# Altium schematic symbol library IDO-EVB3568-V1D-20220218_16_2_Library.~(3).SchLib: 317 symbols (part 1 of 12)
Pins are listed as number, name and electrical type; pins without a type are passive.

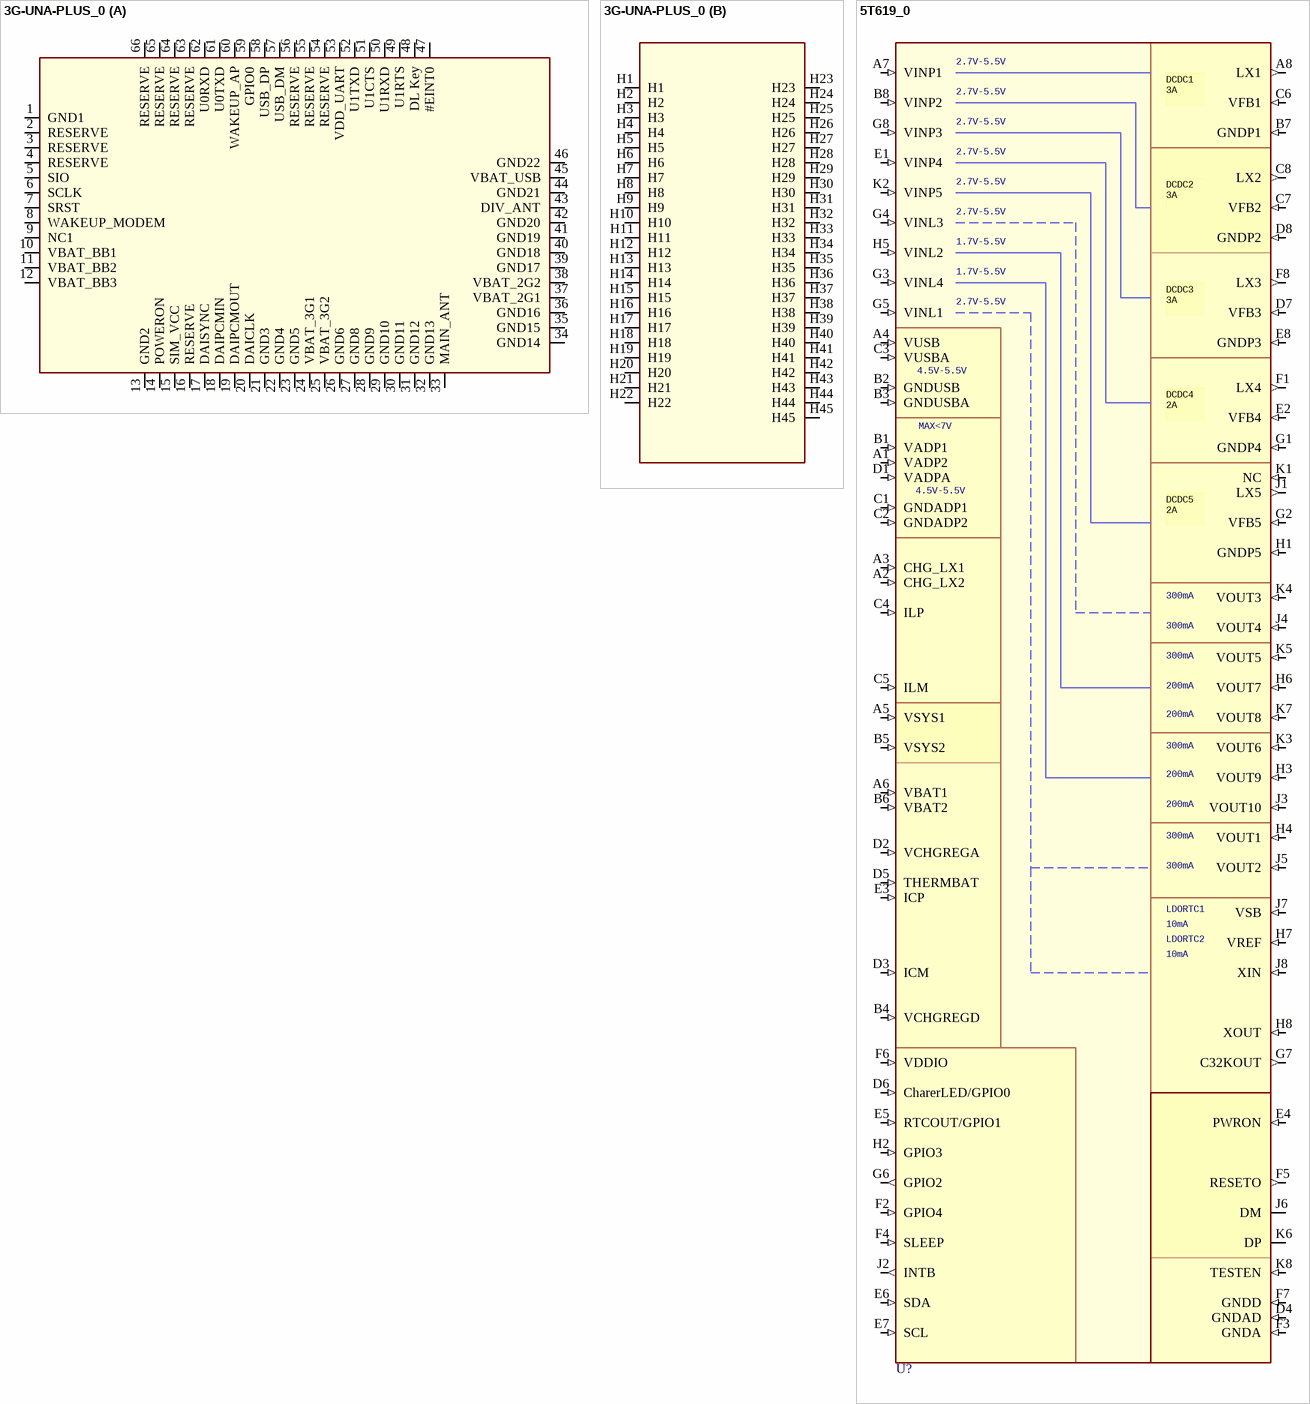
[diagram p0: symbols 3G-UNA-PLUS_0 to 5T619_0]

## 3G-UNA-PLUS_0
designator U?
Altium-Right: 340; Altium-Bottom: 210; Altium-Right1: 110; Altium-Bottom1: 280
part A pins: 1 GND1, 2 RESERVE, 3 RESERVE, 4 RESERVE, 5 SIO, 6 SCLK, 7 SRST, 8 WAKEUP_MODEM, 9 NC1, 10 VBAT_BB1, 11 VBAT_BB2, 12 VBAT_BB3, 13 GND2, 14 POWERON, 15 SIM_VCC, 16 RESERVE, 17 DAISYNC, 18 DAIPCMIN, 19 DAIPCMOUT, 20 DAICLK, 21 GND3, 22 GND4, 23 GND5, 24 VBAT_3G1, 25 VBAT_3G2, 26 GND6, 27 GND8, 28 GND9, 29 GND10, 30 GND11, 31 GND12, 32 GND13, 33 MAIN_ANT, 34 GND14, 35 GND15, 36 GND16, 37 VBAT_2G1, 38 VBAT_2G2, 39 GND17, 40 GND18, 41 GND19, 42 GND20, 43 DIV_ANT, 44 GND21, 45 VBAT_USB, 46 GND22, 47 #EINT0, 48 DL Key, 49 U1RTS, 50 U1RXD, 51 U1CTS, 52 U1TXD, 53 VDD_UART, 54 RESERVE, 55 RESERVE, 56 RESERVE, 57 USB_DM, 58 USB_DP, 59 GPIO0, 60 WAKEUP_AP, 61 U0TXD, 62 U0RXD, 63 RESERVE, 64 RESERVE, 65 RESERVE, 66 RESERVE
part B pins: H1, H2, H3, H4, H5, H6, H7, H8, H9, H10, H11, H12, H13, H14, H15, H16, H17, H18, H19, H20, H21, H22, H23, H24, H25, H26, H27, H28, H29, H30, H31, H32, H33, H34, H35, H36, H37, H38, H39, H40, H41, H42, H43, H44, H45

## 5T619_0
designator U?  (value not drawn)
Altium-Right: 250; Altium-Bottom: 880
pins: A1 VADP2 (in), A2 CHG_LX2 (in), A3 CHG_LX1 (in), A4 VUSB (in), A5 VSYS1 (in), A6 VBAT1 (in), A7 VINP1 (in), A8 LX1 (out), B1 VADP1 (in), B2 GNDUSB (in), B3 GNDUSBA (in), B4 VCHGREGD (in), B5 VSYS2 (in), B6 VBAT2 (in), B7 GNDP1 (in), B8 VINP2 (in), C1 GNDADP1 (in), C2 GNDADP2 (in), C3 VUSBA (in), C4 ILP (in), C5 ILM (in), C6 VFB1 (in), C7 VFB2 (in), C8 LX2 (out), D1 VADPA (in), D2 VCHGREGA (in), D3 ICM (in), D4 GNDAD (in), D5 THERMBAT (in), D6 CharerLED/GPIO0 (in), D7 VFB3 (in), D8 GNDP2 (in), E1 VINP4 (in), E2 VFB4 (in), E3 ICP (in), E4 PWRON (in), E5 RTCOUT/GPIO1 (in), E6 SDA (in), E7 SCL (in), E8 GNDP3 (in), F1 LX4 (out), F2 GPIO4 (in), F3 GNDA (in), F4 SLEEP (in), F5 RESETO (out), F6 VDDIO (in), F7 GNDD (in), F8 LX3 (out), G1 GNDP4 (in), G2 VFB5 (in), G3 VINL4 (in), G4 VINL3 (in), G5 VINL1 (in), G6 GPIO2 (out), G7 C32KOUT (out), G8 VINP3 (in), H1 GNDP5 (in), H2 GPIO3 (in), H3 VOUT9 (in), H4 VOUT1 (in), H5 VINL2 (in), H6 VOUT7 (in), H7 VREF (in), H8 XOUT (in), J1 LX5 (out), J2 INTB (out), J3 VOUT10 (in), J4 VOUT4 (in), J5 VOUT2 (in), J6 DM, J7 VSB (in), J8 XIN (in), K1 NC (in), K2 VINP5 (in), K3 VOUT6 (in), K4 VOUT3 (in), K5 VOUT5 (in), K6 DP, K7 VOUT8 (in), K8 TESTEN (in)

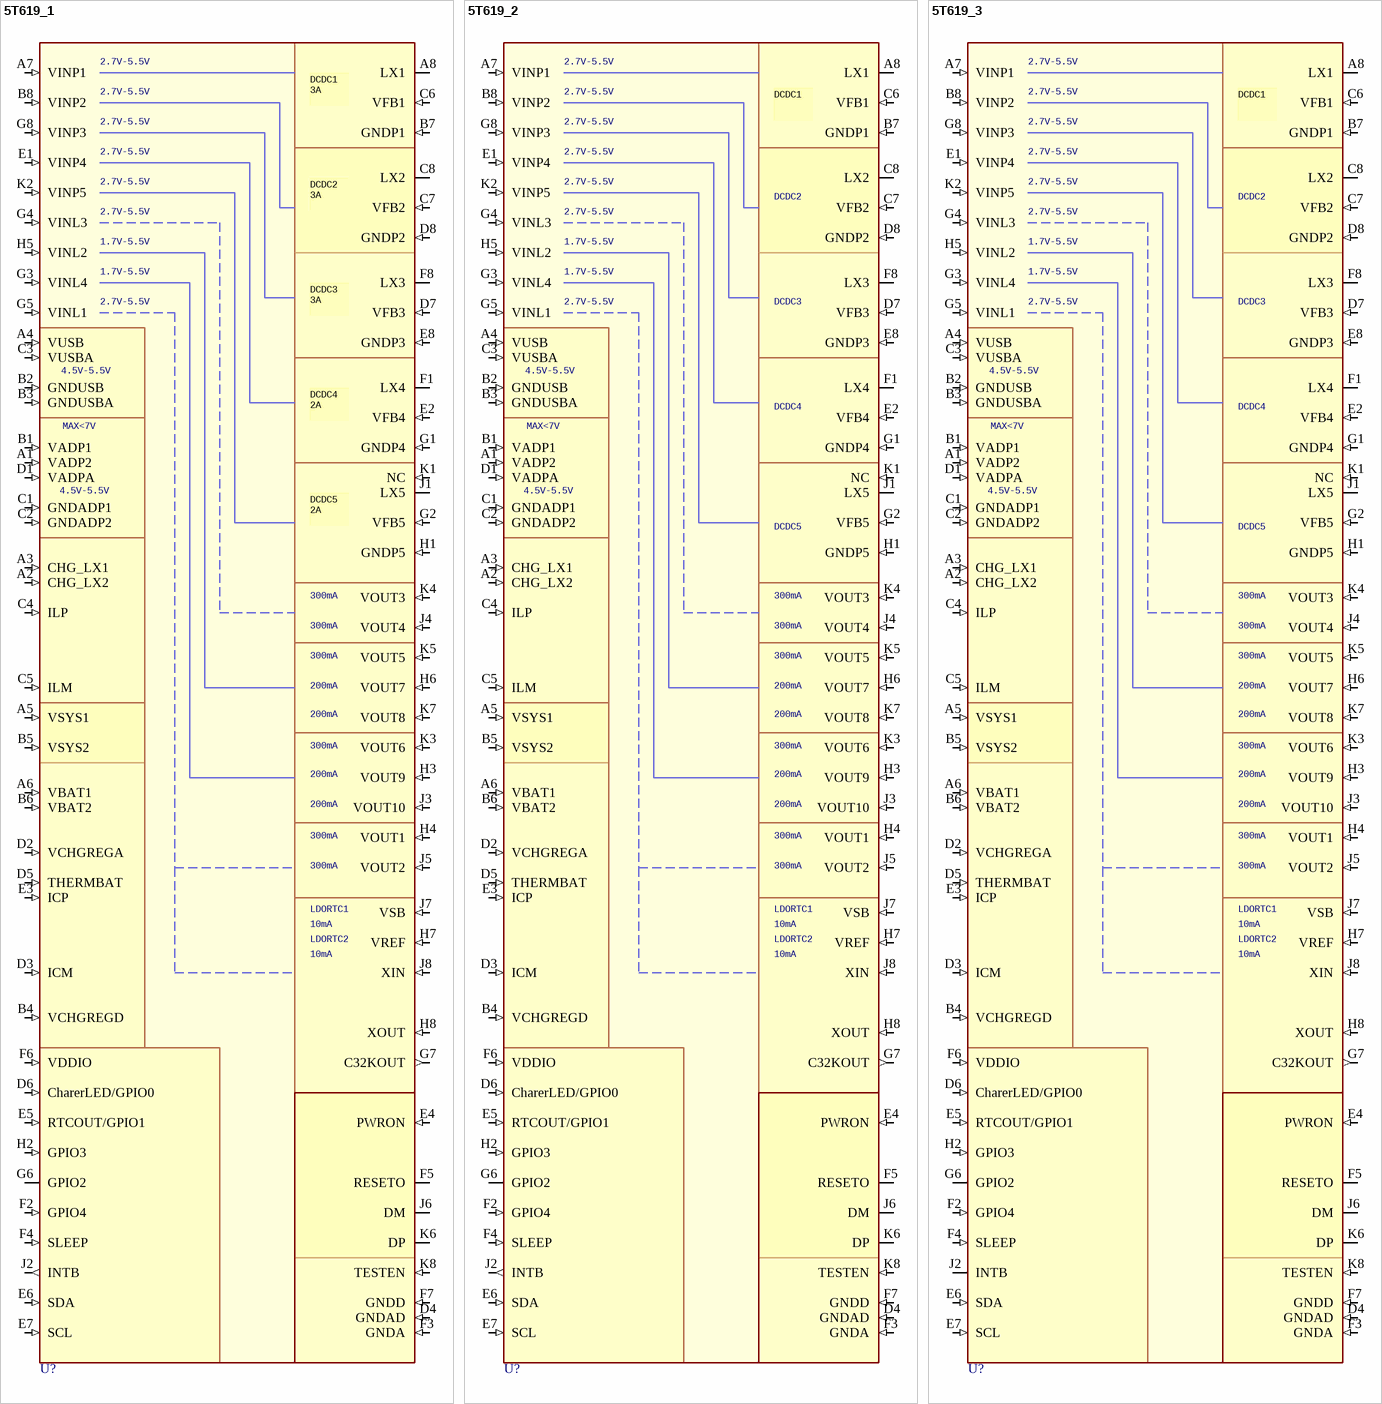
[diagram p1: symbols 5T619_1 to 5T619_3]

## 5T619_1
designator U?  (value not drawn)
Altium-Right: 250; Altium-Bottom: 880
pins: A1 VADP2 (in), A2 CHG_LX2 (in), A3 CHG_LX1 (in), A4 VUSB (in), A5 VSYS1 (in), A6 VBAT1 (in), A7 VINP1 (in), A8 LX1, B1 VADP1 (in), B2 GNDUSB (in), B3 GNDUSBA (in), B4 VCHGREGD (in), B5 VSYS2 (in), B6 VBAT2 (in), B7 GNDP1 (in), B8 VINP2 (in), C1 GNDADP1 (in), C2 GNDADP2 (in), C3 VUSBA (in), C4 ILP (in), C5 ILM (in), C6 VFB1 (in), C7 VFB2 (in), C8 LX2, D1 VADPA (in), D2 VCHGREGA (in), D3 ICM (in), D4 GNDAD (in), D5 THERMBAT (in), D6 CharerLED/GPIO0 (in), D7 VFB3 (in), D8 GNDP2 (in), E1 VINP4 (in), E2 VFB4 (in), E3 ICP (in), E4 PWRON (in), E5 RTCOUT/GPIO1 (in), E6 SDA (in), E7 SCL (in), E8 GNDP3 (in), F1 LX4, F2 GPIO4 (in), F3 GNDA (in), F4 SLEEP (in), F5 RESETO, F6 VDDIO (in), F7 GNDD (in), F8 LX3, G1 GNDP4 (in), G2 VFB5 (in), G3 VINL4 (in), G4 VINL3 (in), G5 VINL1 (in), G6 GPIO2, G7 C32KOUT (out), G8 VINP3 (in), H1 GNDP5 (in), H2 GPIO3 (in), H3 VOUT9 (in), H4 VOUT1 (in), H5 VINL2 (in), H6 VOUT7 (in), H7 VREF (in), H8 XOUT (in), J1 LX5, J2 INTB (out), J3 VOUT10 (in), J4 VOUT4 (in), J5 VOUT2 (in), J6 DM, J7 VSB (in), J8 XIN (in), K1 NC (in), K2 VINP5 (in), K3 VOUT6 (in), K4 VOUT3 (in), K5 VOUT5 (in), K6 DP, K7 VOUT8 (in), K8 TESTEN (in)

## 5T619_2
designator U?  (value not drawn)
Altium-Right: 250; Altium-Bottom: 880
pins: A1 VADP2 (in), A2 CHG_LX2 (in), A3 CHG_LX1 (in), A4 VUSB (in), A5 VSYS1 (in), A6 VBAT1 (in), A7 VINP1 (in), A8 LX1, B1 VADP1 (in), B2 GNDUSB (in), B3 GNDUSBA (in), B4 VCHGREGD (in), B5 VSYS2 (in), B6 VBAT2 (in), B7 GNDP1 (in), B8 VINP2 (in), C1 GNDADP1 (in), C2 GNDADP2 (in), C3 VUSBA (in), C4 ILP (in), C5 ILM (in), C6 VFB1 (in), C7 VFB2 (in), C8 LX2, D1 VADPA (in), D2 VCHGREGA (in), D3 ICM (in), D4 GNDAD (in), D5 THERMBAT (in), D6 CharerLED/GPIO0 (in), D7 VFB3 (in), D8 GNDP2 (in), E1 VINP4 (in), E2 VFB4 (in), E3 ICP (in), E4 PWRON (in), E5 RTCOUT/GPIO1 (in), E6 SDA (in), E7 SCL (in), E8 GNDP3 (in), F1 LX4, F2 GPIO4 (in), F3 GNDA (in), F4 SLEEP (in), F5 RESETO, F6 VDDIO (in), F7 GNDD (in), F8 LX3, G1 GNDP4 (in), G2 VFB5 (in), G3 VINL4 (in), G4 VINL3 (in), G5 VINL1 (in), G6 GPIO2, G7 C32KOUT (out), G8 VINP3 (in), H1 GNDP5 (in), H2 GPIO3 (in), H3 VOUT9 (in), H4 VOUT1 (in), H5 VINL2 (in), H6 VOUT7 (in), H7 VREF (in), H8 XOUT (in), J1 LX5, J2 INTB (out), J3 VOUT10 (in), J4 VOUT4 (in), J5 VOUT2 (in), J6 DM, J7 VSB (in), J8 XIN (in), K1 NC (in), K2 VINP5 (in), K3 VOUT6 (in), K4 VOUT3 (in), K5 VOUT5 (in), K6 DP, K7 VOUT8 (in), K8 TESTEN (in)

## 5T619_3
designator U?  (value not drawn)
Altium-Right: 250; Altium-Bottom: 880
pins: A1 VADP2 (in), A2 CHG_LX2 (in), A3 CHG_LX1 (in), A4 VUSB (in), A5 VSYS1 (in), A6 VBAT1 (in), A7 VINP1 (in), A8 LX1, B1 VADP1 (in), B2 GNDUSB (in), B3 GNDUSBA (in), B4 VCHGREGD (in), B5 VSYS2 (in), B6 VBAT2 (in), B7 GNDP1 (in), B8 VINP2 (in), C1 GNDADP1 (in), C2 GNDADP2 (in), C3 VUSBA (in), C4 ILP (in), C5 ILM (in), C6 VFB1 (in), C7 VFB2 (in), C8 LX2, D1 VADPA (in), D2 VCHGREGA (in), D3 ICM (in), D4 GNDAD (in), D5 THERMBAT (in), D6 CharerLED/GPIO0 (in), D7 VFB3 (in), D8 GNDP2 (in), E1 VINP4 (in), E2 VFB4 (in), E3 ICP (in), E4 PWRON (in), E5 RTCOUT/GPIO1 (in), E6 SDA (in), E7 SCL (in), E8 GNDP3 (in), F1 LX4, F2 GPIO4 (in), F3 GNDA (in), F4 SLEEP (in), F5 RESETO, F6 VDDIO (in), F7 GNDD (in), F8 LX3, G1 GNDP4 (in), G2 VFB5 (in), G3 VINL4 (in), G4 VINL3 (in), G5 VINL1 (in), G6 GPIO2, G7 C32KOUT (out), G8 VINP3 (in), H1 GNDP5 (in), H2 GPIO3 (in), H3 VOUT9 (in), H4 VOUT1 (in), H5 VINL2 (in), H6 VOUT7 (in), H7 VREF (in), H8 XOUT (in), J1 LX5, J2 INTB, J3 VOUT10 (in), J4 VOUT4 (in), J5 VOUT2 (in), J6 DM, J7 VSB (in), J8 XIN (in), K1 NC (in), K2 VINP5 (in), K3 VOUT6 (in), K4 VOUT3 (in), K5 VOUT5 (in), K6 DP, K7 VOUT8 (in), K8 TESTEN (in)

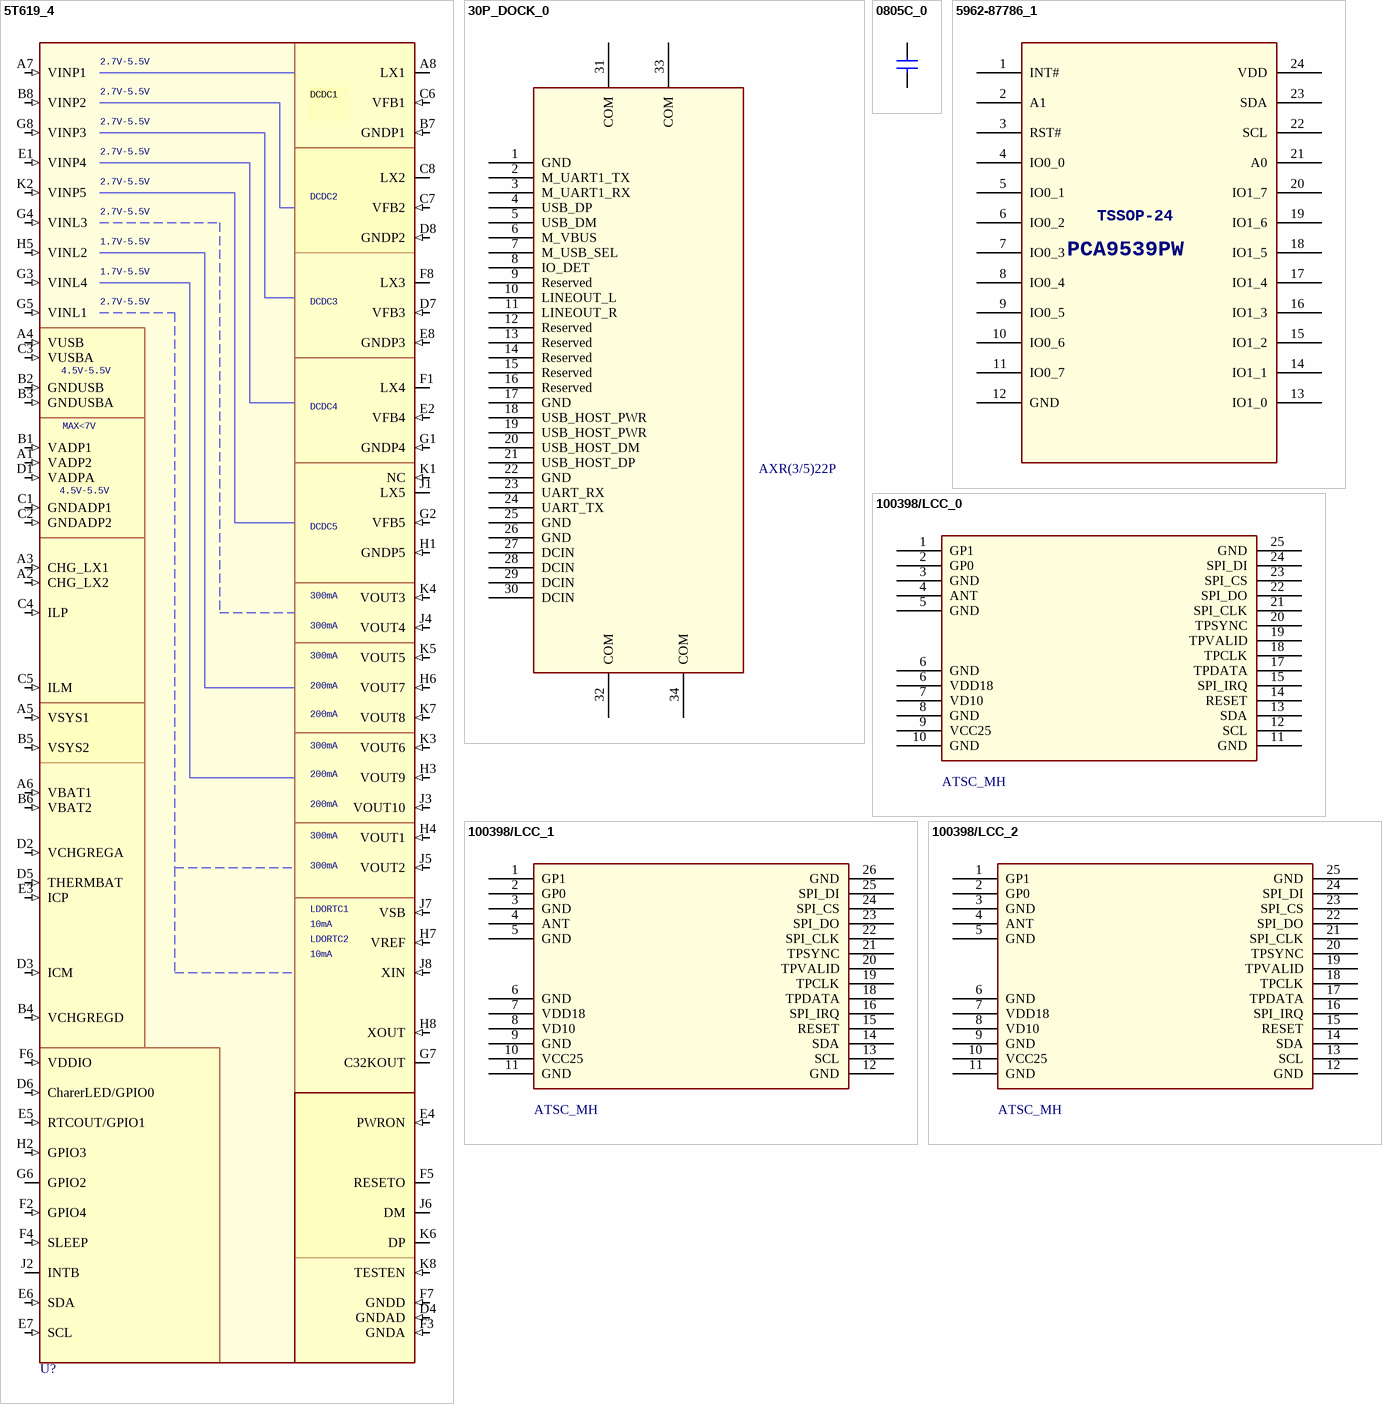
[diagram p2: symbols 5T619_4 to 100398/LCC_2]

## 5T619_4
designator U?  (value not drawn)
Altium-Right: 250; Altium-Bottom: 880
pins: A1 VADP2 (in), A2 CHG_LX2 (in), A3 CHG_LX1 (in), A4 VUSB (in), A5 VSYS1 (in), A6 VBAT1 (in), A7 VINP1 (in), A8 LX1, B1 VADP1 (in), B2 GNDUSB (in), B3 GNDUSBA (in), B4 VCHGREGD (in), B5 VSYS2 (in), B6 VBAT2 (in), B7 GNDP1 (in), B8 VINP2 (in), C1 GNDADP1 (in), C2 GNDADP2 (in), C3 VUSBA (in), C4 ILP (in), C5 ILM (in), C6 VFB1 (in), C7 VFB2 (in), C8 LX2, D1 VADPA (in), D2 VCHGREGA (in), D3 ICM (in), D4 GNDAD (in), D5 THERMBAT (in), D6 CharerLED/GPIO0 (in), D7 VFB3 (in), D8 GNDP2 (in), E1 VINP4 (in), E2 VFB4 (in), E3 ICP (in), E4 PWRON (in), E5 RTCOUT/GPIO1 (in), E6 SDA (in), E7 SCL (in), E8 GNDP3 (in), F1 LX4, F2 GPIO4 (in), F3 GNDA (in), F4 SLEEP (in), F5 RESETO, F6 VDDIO (in), F7 GNDD (in), F8 LX3, G1 GNDP4 (in), G2 VFB5 (in), G3 VINL4 (in), G4 VINL3 (in), G5 VINL1 (in), G6 GPIO2, G7 C32KOUT, G8 VINP3 (in), H1 GNDP5 (in), H2 GPIO3 (in), H3 VOUT9 (in), H4 VOUT1 (in), H5 VINL2 (in), H6 VOUT7 (in), H7 VREF (in), H8 XOUT (in), J1 LX5, J2 INTB, J3 VOUT10 (in), J4 VOUT4 (in), J5 VOUT2 (in), J6 DM, J7 VSB (in), J8 XIN (in), K1 NC (in), K2 VINP5 (in), K3 VOUT6 (in), K4 VOUT3 (in), K5 VOUT5 (in), K6 DP, K7 VOUT8 (in), K8 TESTEN (in)

## 30P_DOCK_0
designator CON?, comment AXR(3/5)22P
Altium-Right: 140; Altium-Bottom: 390
footprint 30P_DOCK_1
pins: 1 GND, 2 M_UART1_TX, 3 M_UART1_RX, 4 USB_DP, 5 USB_DM, 6 M_VBUS, 7 M_USB_SEL, 8 IO_DET, 9 Reserved, 10 LINEOUT_L, 11 LINEOUT_R, 12 Reserved, 13 Reserved, 14 Reserved, 15 Reserved, 16 Reserved, 17 GND, 18 USB_HOST_PWR, 19 USB_HOST_PWR, 20 USB_HOST_DM, 21 USB_HOST_DP, 22 GND, 23 UART_RX, 24 UART_TX, 25 GND, 26 GND, 27 DCIN, 28 DCIN, 29 DCIN, 30 DCIN, 31 COM, 32 COM, 33 COM, 34 COM

## 0805C_0
designator C?
Altium-Right: 20; Altium-Bottom: 10
footprint 0805C
pins: 1, 2

## 5962-87786_1
designator U?
Altium-Right: 170; Altium-Bottom: 280
pins: 1 INT#, 2 A1, 3 RST#, 4 IO0_0, 5 IO0_1, 6 IO0_2, 7 IO0_3, 8 IO0_4, 9 IO0_5, 10 IO0_6, 11 IO0_7, 12 GND, 13 IO1_0, 14 IO1_1, 15 IO1_2, 16 IO1_3, 17 IO1_4, 18 IO1_5, 19 IO1_6, 20 IO1_7, 21 A0, 22 SCL, 23 SDA, 24 VDD

## 100398/LCC_0
designator U?, comment ATSC_MH
Altium-Right: 210; Altium-Bottom: 150
pins: 1 GP1, 2 GP0, 3 GND, 4 ANT, 5 GND, 6 VDD18, 6 GND, 7 VD10, 8 GND, 9 VCC25, 10 GND, 11 GND, 12 SCL, 13 SDA, 14 RESET, 15 SPI_IRQ, 17 TPDATA, 18 TPCLK, 19 TPVALID, 20 TPSYNC, 21 SPI_CLK, 22 SPI_DO, 23 SPI_CS, 24 SPI_DI, 25 GND

## 100398/LCC_1
designator U?, comment ATSC_MH
Altium-Right: 210; Altium-Bottom: 150
pins: 1 GP1, 2 GP0, 3 GND, 4 ANT, 5 GND, 6 GND, 7 VDD18, 8 VD10, 9 GND, 10 VCC25, 11 GND, 12 GND, 13 SCL, 14 SDA, 15 RESET, 16 SPI_IRQ, 18 TPDATA, 19 TPCLK, 20 TPVALID, 21 TPSYNC, 22 SPI_CLK, 23 SPI_DO, 24 SPI_CS, 25 SPI_DI, 26 GND

## 100398/LCC_2
designator U?, comment ATSC_MH
Altium-Right: 210; Altium-Bottom: 150
pins: 1 GP1, 2 GP0, 3 GND, 4 ANT, 5 GND, 6 GND, 7 VDD18, 8 VD10, 9 GND, 10 VCC25, 11 GND, 12 GND, 13 SCL, 14 SDA, 15 RESET, 16 SPI_IRQ, 17 TPDATA, 18 TPCLK, 19 TPVALID, 20 TPSYNC, 21 SPI_CLK, 22 SPI_DO, 23 SPI_CS, 24 SPI_DI, 25 GND

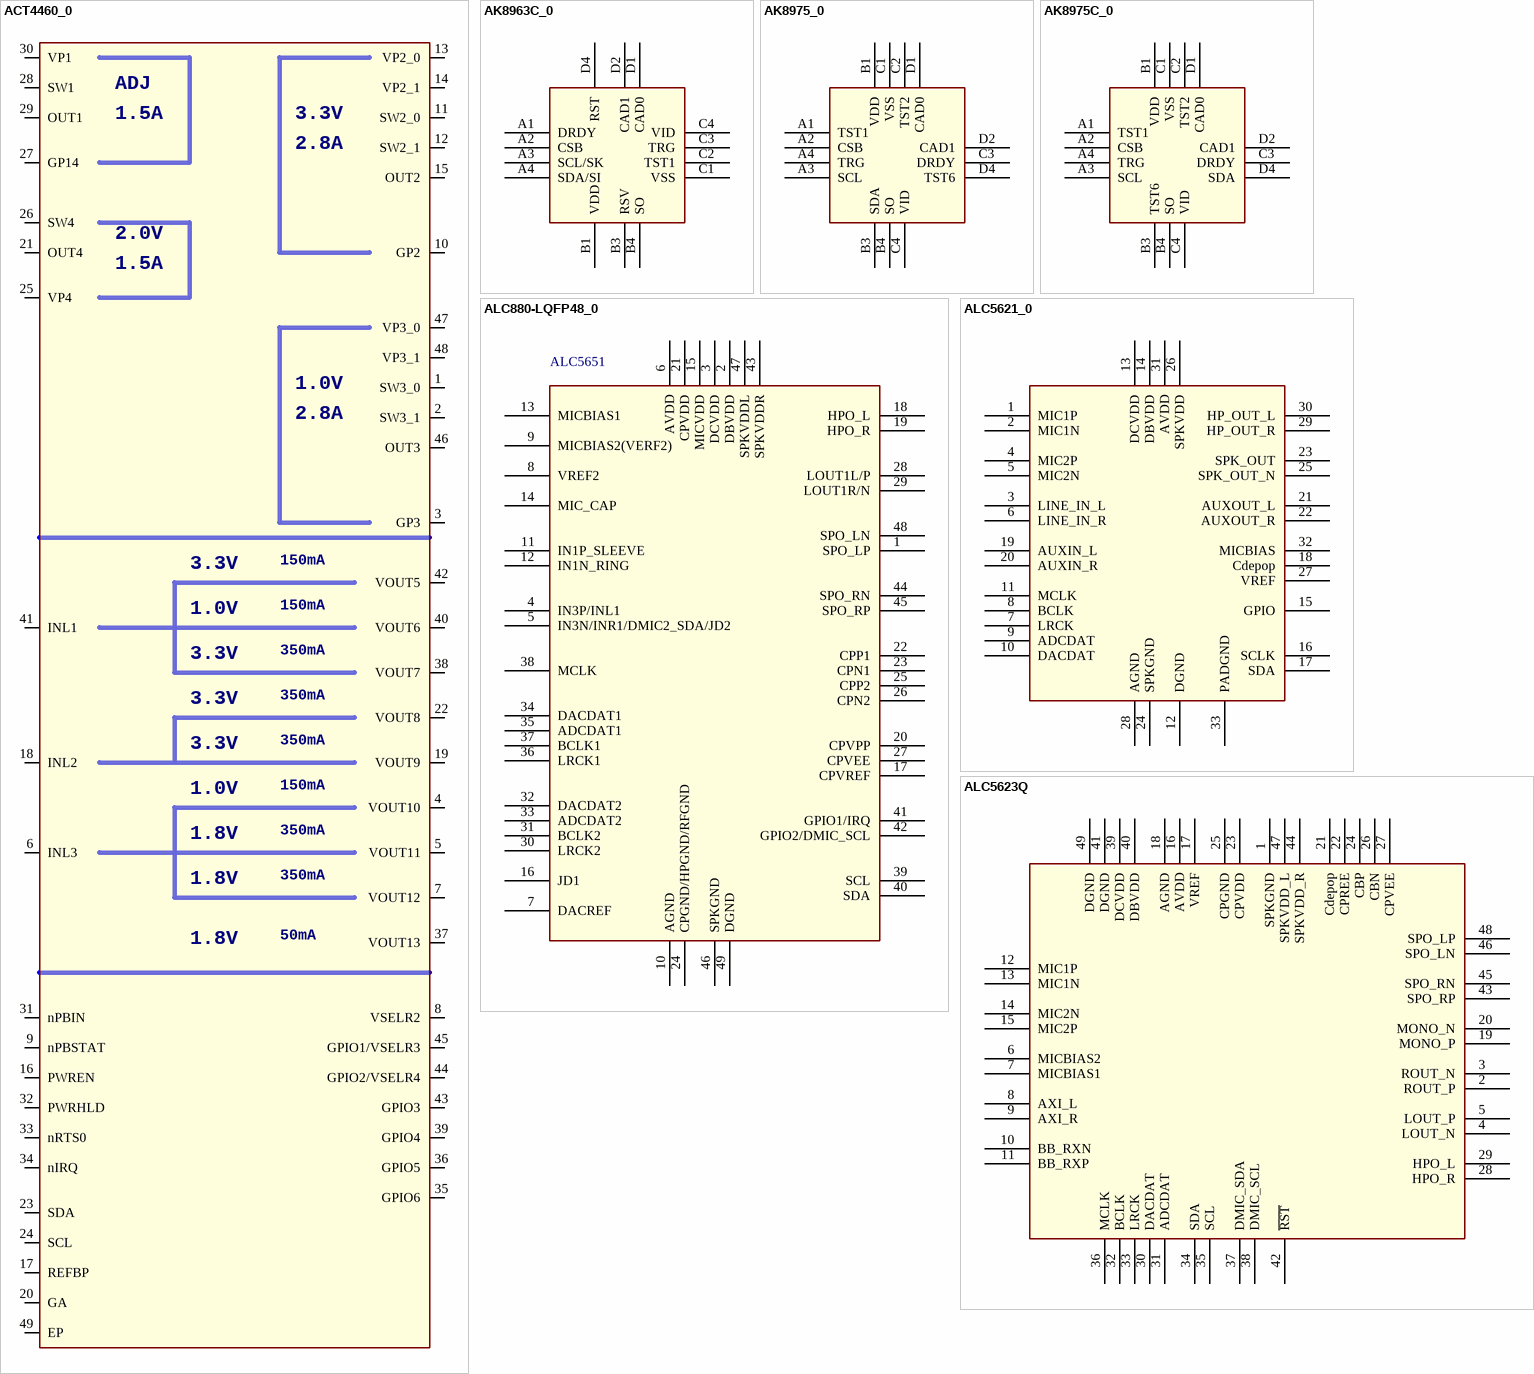
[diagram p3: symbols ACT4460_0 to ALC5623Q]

## ACT4460_0
designator U?
Altium-Right: 260; Altium-Bottom: 870
pins: 1 SW3_0, 2 SW3_1, 3 GP3, 4 VOUT10, 5 VOUT11, 6 INL3, 7 VOUT12, 8 VSELR2, 9 nPBSTAT, 10 GP2, 11 SW2_0, 12 SW2_1, 13 VP2_0, 14 VP2_1, 15 OUT2, 16 PWREN, 17 REFBP, 18 INL2, 19 VOUT9, 20 GA, 21 OUT4, 22 VOUT8, 23 SDA, 24 SCL, 25 VP4, 26 SW4, 27 GP14, 28 SW1, 29 OUT1, 30 VP1, 31 nPBIN, 32 PWRHLD, 33 nRTS0, 34 nIRQ, 35 GPIO6, 36 GPIO5, 37 VOUT13, 38 VOUT7, 39 GPIO4, 40 VOUT6, 41 INL1, 42 VOUT5, 43 GPIO3, 44 GPIO2/VSELR4, 45 GPIO1/VSELR3, 46 OUT3, 47 VP3_0, 48 VP3_1, 49 EP

## AK8963C_0
designator U?
Altium-Right: 90
footprint AK8975B
pins: A1 DRDY, A2 CSB, A3 SCL/SK, A4 SDA/SI, B1 VDD, B3 RSV, B4 SO, C1 VSS, C2 TST1, C3 TRG, C4 VID, D1 CAD0, D2 CAD1, D4 RST

## AK8975_0
designator U?
Altium-Right: 90
footprint QFN16-4X4
pins: A1 TST1, A2 CSB, A3 SCL, A4 TRG, B1 VDD, B3 SDA, B4 SO, C1 VSS, C2 TST2, C3 DRDY, C4 VID, D1 CAD0, D2 CAD1, D4 TST6

## AK8975C_0
designator U?
Altium-Right: 90
footprint AK8975B
pins: A1 TST1, A2 CSB, A3 SCL, A4 TRG, B1 VDD, B3 TST6, B4 SO, C1 VSS, C2 TST2, C3 DRDY, C4 VID, D1 CAD0, D2 CAD1, D4 SDA

## ALC880-LQFP48_0
designator U?, comment ALC5651
Altium-Right: 220; Altium-Bottom: 370
pins: 1 SPO_LP, 2 DBVDD, 3 DCVDD, 4 IN3P/INL1, 5 IN3N/INR1/DMIC2_SDA/JD2, 6 AVDD, 7 DACREF, 8 VREF2, 9 MICBIAS2(VERF2), 10 AGND, 11 IN1P_SLEEVE, 12 IN1N_RING, 13 MICBIAS1, 14 MIC_CAP, 15 MICVDD, 16 JD1, 17 CPVREF, 18 HPO_L, 19 HPO_R, 20 CPVPP, 21 CPVDD, 22 CPP1, 23 CPN1, 24 CPGND/HPGND/RFGND, 25 CPP2, 26 CPN2, 27 CPVEE, 28 LOUT1L/P, 29 LOUT1R/N, 30 LRCK2, 31 BCLK2, 32 DACDAT2, 33 ADCDAT2, 34 DACDAT1, 35 ADCDAT1, 36 LRCK1, 37 BCLK1, 38 MCLK, 39 SCL, 40 SDA, 41 GPIO1/IRQ, 42 GPIO2/DMIC_SCL, 43 SPKVDDR, 44 SPO_RN, 45 SPO_RP, 46 SPKGND, 47 SPKVDDL, 48 SPO_LN, 49 DGND

## ALC5621_0
designator U?
Altium-Right: 170; Altium-Bottom: 210
footprint QFN32
pins: 1 MIC1P, 2 MIC1N, 3 LINE_IN_L, 4 MIC2P, 5 MIC2N, 6 LINE_IN_R, 7 LRCK, 8 BCLK, 9 ADCDAT, 10 DACDAT, 11 MCLK, 12 DGND, 13 DCVDD, 14 DBVDD, 15 GPIO, 16 SCLK, 17 SDA, 18 Cdepop, 19 AUXIN_L, 20 AUXIN_R, 21 AUXOUT_L, 22 AUXOUT_R, 23 SPK_OUT, 24 SPKGND, 25 SPK_OUT_N, 26 SPKVDD, 27 VREF, 28 AGND, 29 HP_OUT_R, 30 HP_OUT_L, 31 AVDD, 32 MICBIAS, 33 PADGND

## ALC5623Q
designator U?
Altium-Right: 290; Altium-Bottom: 250
footprint QFN48-6X6
pins: 1 SPKGND, 2 ROUT_P, 3 ROUT_N, 4 LOUT_N, 5 LOUT_P, 6 MICBIAS2, 7 MICBIAS1, 8 AXI_L, 9 AXI_R, 10 BB_RXN, 11 BB_RXP, 12 MIC1P, 13 MIC1N, 14 MIC2N, 15 MIC2P, 16 AVDD, 17 VREF, 18 AGND, 19 MONO_P, 20 MONO_N, 21 Cdepop, 22 CPREE, 23 CPVDD, 24 CBP, 25 CPGND, 26 CBN, 27 CPVEE, 28 HPO_R, 29 HPO_L, 30 DACDAT, 31 ADCDAT, 32 BCLK, 33 LRCK, 34 SDA, 35 SCL, 36 MCLK, 37 DMIC_SDA, 38 DMIC_SCL, 39 DCVDD, 40 DBVDD, 41 DGND, 42 ~{RST}, 43 SPO_RP, 44 SPKVDD_R, 45 SPO_RN, 46 SPO_LN, 47 SPKVDD_L, 48 SPO_LP, 49 DGND

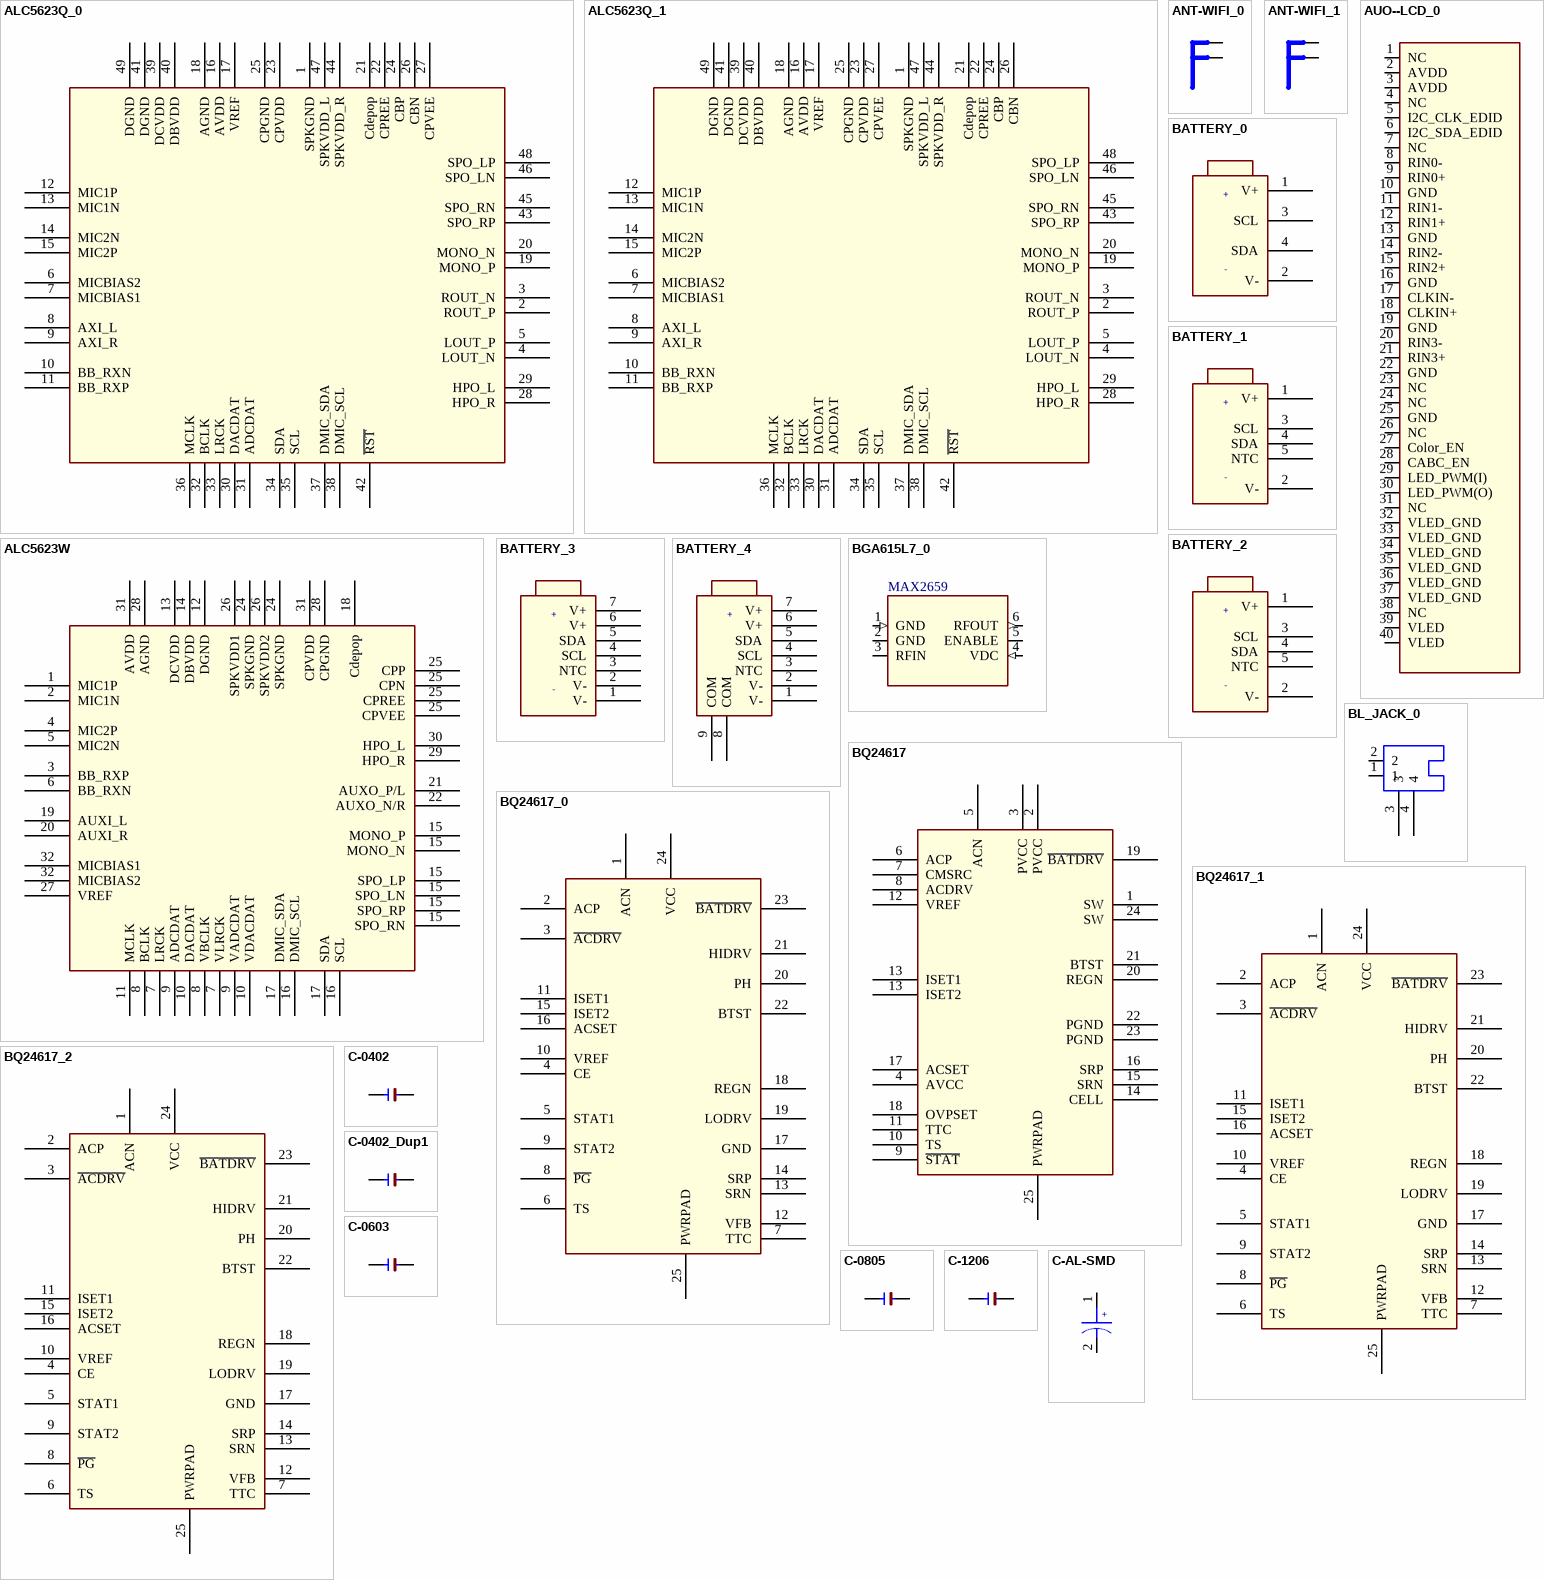
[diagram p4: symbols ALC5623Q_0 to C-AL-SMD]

## ALC5623Q_0
designator U?
Altium-Right: 290; Altium-Bottom: 250
footprint QFN48-6X6
pins: 1 SPKGND, 2 ROUT_P, 3 ROUT_N, 4 LOUT_N, 5 LOUT_P, 6 MICBIAS2, 7 MICBIAS1, 8 AXI_L, 9 AXI_R, 10 BB_RXN, 11 BB_RXP, 12 MIC1P, 13 MIC1N, 14 MIC2N, 15 MIC2P, 16 AVDD, 17 VREF, 18 AGND, 19 MONO_P, 20 MONO_N, 21 Cdepop, 22 CPREE, 23 CPVDD, 24 CBP, 25 CPGND, 26 CBN, 27 CPVEE, 28 HPO_R, 29 HPO_L, 30 DACDAT, 31 ADCDAT, 32 BCLK, 33 LRCK, 34 SDA, 35 SCL, 36 MCLK, 37 DMIC_SDA, 38 DMIC_SCL, 39 DCVDD, 40 DBVDD, 41 DGND, 42 ~{RST}, 43 SPO_RP, 44 SPKVDD_R, 45 SPO_RN, 46 SPO_LN, 47 SPKVDD_L, 48 SPO_LP, 49 DGND

## ALC5623Q_1
designator U?
Altium-Right: 290; Altium-Bottom: 250
footprint QFN48-6X6
pins: 1 SPKGND, 2 ROUT_P, 3 ROUT_N, 4 LOUT_N, 5 LOUT_P, 6 MICBIAS2, 7 MICBIAS1, 8 AXI_L, 9 AXI_R, 10 BB_RXN, 11 BB_RXP, 12 MIC1P, 13 MIC1N, 14 MIC2N, 15 MIC2P, 16 AVDD, 17 VREF, 18 AGND, 19 MONO_P, 20 MONO_N, 21 Cdepop, 22 CPREE, 23 CPVDD, 24 CBP, 25 CPGND, 26 CBN, 27 CPVEE, 28 HPO_R, 29 HPO_L, 30 DACDAT, 31 ADCDAT, 32 BCLK, 33 LRCK, 34 SDA, 35 SCL, 36 MCLK, 37 DMIC_SDA, 38 DMIC_SCL, 39 DCVDD, 40 DBVDD, 41 DGND, 42 ~{RST}, 43 SPO_RP, 44 SPKVDD_R, 45 SPO_RN, 46 SPO_LN, 47 SPKVDD_L, 48 SPO_LP, 49 DGND

## ALC5623W
designator U?
Altium-Right: 230
footprint GBA49
pins: 1 MIC1P, 2 MIC1N, 3 BB_RXP, 4 MIC2P, 5 MIC2N, 6 BB_RXN, 7 LRCK, 7 VLRCK, 8 BCLK, 8 VBCLK, 9 ADCDAT, 9 VADCDAT, 10 DACDAT, 10 VDACDAT, 11 MCLK, 12 DGND, 13 DCVDD, 14 DBVDD, 15 SPO_RN, 15 SPO_RP, 15 SPO_LP, 15 SPO_LN, 15 MONO_P, 15 MONO_N, 16 SCL, 16 DMIC_SCL, 17 SDA, 17 DMIC_SDA, 18 Cdepop, 19 AUXI_L, 20 AUXI_R, 21 AUXO_P/L, 22 AUXO_N/R, 24 SPKGND, 24 SPKGND, 25 CPVEE, 25 CPREE, 25 CPN, 25 CPP, 26 SPKVDD1, 26 SPKVDD2, 27 VREF, 28 AGND, 28 CPGND, 29 HPO_R, 30 HPO_L, 31 AVDD, 31 CPVDD, 32 MICBIAS1, 32 MICBIAS2

## ANT-WIFI_0
designator C?
Altium-Right: 20; Altium-Bottom: 32
pins: 1, 2

## ANT-WIFI_1
designator C?
Altium-Right: 20; Altium-Bottom: 32
pins: 1, 2

## AUO--LCD_0
designator U?
Altium-Right: 80; Altium-Bottom: 420
pins: 1 NC, 2 AVDD, 3 AVDD, 4 NC, 5 I2C_CLK_EDID, 6 I2C_SDA_EDID, 7 NC, 8 RIN0-, 9 RIN0+, 10 GND, 11 RIN1-, 12 RIN1+, 13 GND, 14 RIN2-, 15 RIN2+, 16 GND, 17 CLKIN-, 18 CLKIN+, 19 GND, 20 RIN3-, 21 RIN3+, 22 GND, 23 NC, 24 NC, 25 GND, 26 NC, 27 Color_EN, 28 CABC_EN, 29 LED_PWM(I), 30 LED_PWM(O), 31 NC, 32 VLED_GND, 33 VLED_GND, 34 VLED_GND, 35 VLED_GND, 36 VLED_GND, 37 VLED_GND, 38 NC, 39 VLED, 40 VLED

## BATTERY_0
designator BT?
Altium-Right: 50; Altium-Bottom: 90
pins: 1 V+, 2 V-, 3 SCL, 4 SDA

## BATTERY_1
designator BT?
Altium-Right: 50; Altium-Bottom: 90
pins: 1 V+, 2 V-, 3 SCL, 4 SDA, 5 NTC

## BATTERY_2
designator BT?
Altium-Right: 50; Altium-Bottom: 90
pins: 1 V+, 2 V-, 3 SCL, 4 SDA, 5 NTC

## BATTERY_3
designator BT?
Altium-Right: 50; Altium-Bottom: 90
pins: 1 V-, 2 V-, 3 NTC, 4 SCL, 5 SDA, 6 V+, 7 V+

## BATTERY_4
designator BT?
Altium-Right: 50; Altium-Bottom: 90
pins: 1 V- (power), 2 V- (power), 3 NTC, 4 SCL, 5 SDA, 6 V+ (power), 7 V+ (power), 8 COM, 9 COM

## BGA615L7_0
designator U?, comment MAX2659
Altium-Right: 80; Altium-Bottom: 60
footprint P-TSLP-7-1
pins: 1 GND (in), 2 GND, 3 RFIN (power), 4 VDC (in), 5 ENABLE (power), 6 RFOUT (out)

## BL_JACK_0
designator J?
Altium-Right: 40; Altium-Bottom: 30
pins: 1, 2, 3, 4

## BQ24617
designator U?
Altium-Right: 130; Altium-Bottom: 230
footprint QFN24
pins: 1 SW, 2 PVCC, 3 PVCC, 4 AVCC, 5 ACN, 6 ACP, 7 CMSRC, 8 ACDRV, 9 ~{STAT}, 10 TS, 11 TTC, 12 VREF, 13 ISET1, 13 ISET2, 14 CELL, 15 SRN, 16 SRP, 17 ACSET, 18 OVPSET, 19 ~{BATDRV}, 20 REGN, 21 BTST, 22 PGND, 23 PGND, 24 SW, 25 PWRPAD

## BQ24617_0
designator U?
Altium-Right: 130; Altium-Bottom: 250
footprint QFN24
pins: 1 ACN, 2 ACP, 3 ~{ACDRV}, 4 CE, 5 STAT1, 6 TS, 7 TTC, 8 ~{PG}, 9 STAT2, 10 VREF, 11 ISET1, 12 VFB, 13 SRN, 14 SRP, 15 ISET2, 16 ACSET, 17 GND, 18 REGN, 19 LODRV, 20 PH, 21 HIDRV, 22 BTST, 23 ~{BATDRV}, 24 VCC, 25 PWRPAD

## BQ24617_1
designator U?
Altium-Right: 130; Altium-Bottom: 250
footprint QFN24
pins: 1 ACN, 2 ACP, 3 ~{ACDRV}, 4 CE, 5 STAT1, 6 TS, 7 TTC, 8 ~{PG}, 9 STAT2, 10 VREF, 11 ISET1, 12 VFB, 13 SRN, 14 SRP, 15 ISET2, 16 ACSET, 17 GND, 18 REGN, 19 LODRV, 20 PH, 21 HIDRV, 22 BTST, 23 ~{BATDRV}, 24 VCC, 25 PWRPAD

## BQ24617_2
designator U?
Altium-Right: 130; Altium-Bottom: 250
footprint QFN24
pins: 1 ACN, 2 ACP, 3 ~{ACDRV}, 4 CE, 5 STAT1, 6 TS, 7 TTC, 8 ~{PG}, 9 STAT2, 10 VREF, 11 ISET1, 12 VFB, 13 SRN, 14 SRP, 15 ISET2, 16 ACSET, 17 GND, 18 REGN, 19 LODRV, 20 PH, 21 HIDRV, 22 BTST, 23 ~{BATDRV}, 24 VCC, 25 PWRPAD

## C-0402
designator C?
Altium-Right: 10; Altium-Bottom: 20
footprint 1206
pins: 1, 2

## C-0402_Dup1
designator C?
Altium-Right: 10; Altium-Bottom: 20
footprint 1206
pins: 1, 2

## C-0603
designator C?
Altium-Right: 10; Altium-Bottom: 20
footprint 1206
pins: 1, 2

## C-0805
designator C?
Altium-Right: 10; Altium-Bottom: 20
footprint 1206
pins: 1, 2

## C-1206
designator C?
Altium-Right: 10; Altium-Bottom: 20
footprint 1206
pins: 1, 2

## C-AL-SMD
designator CP?
Altium-Right: 20
pins: 1, 2

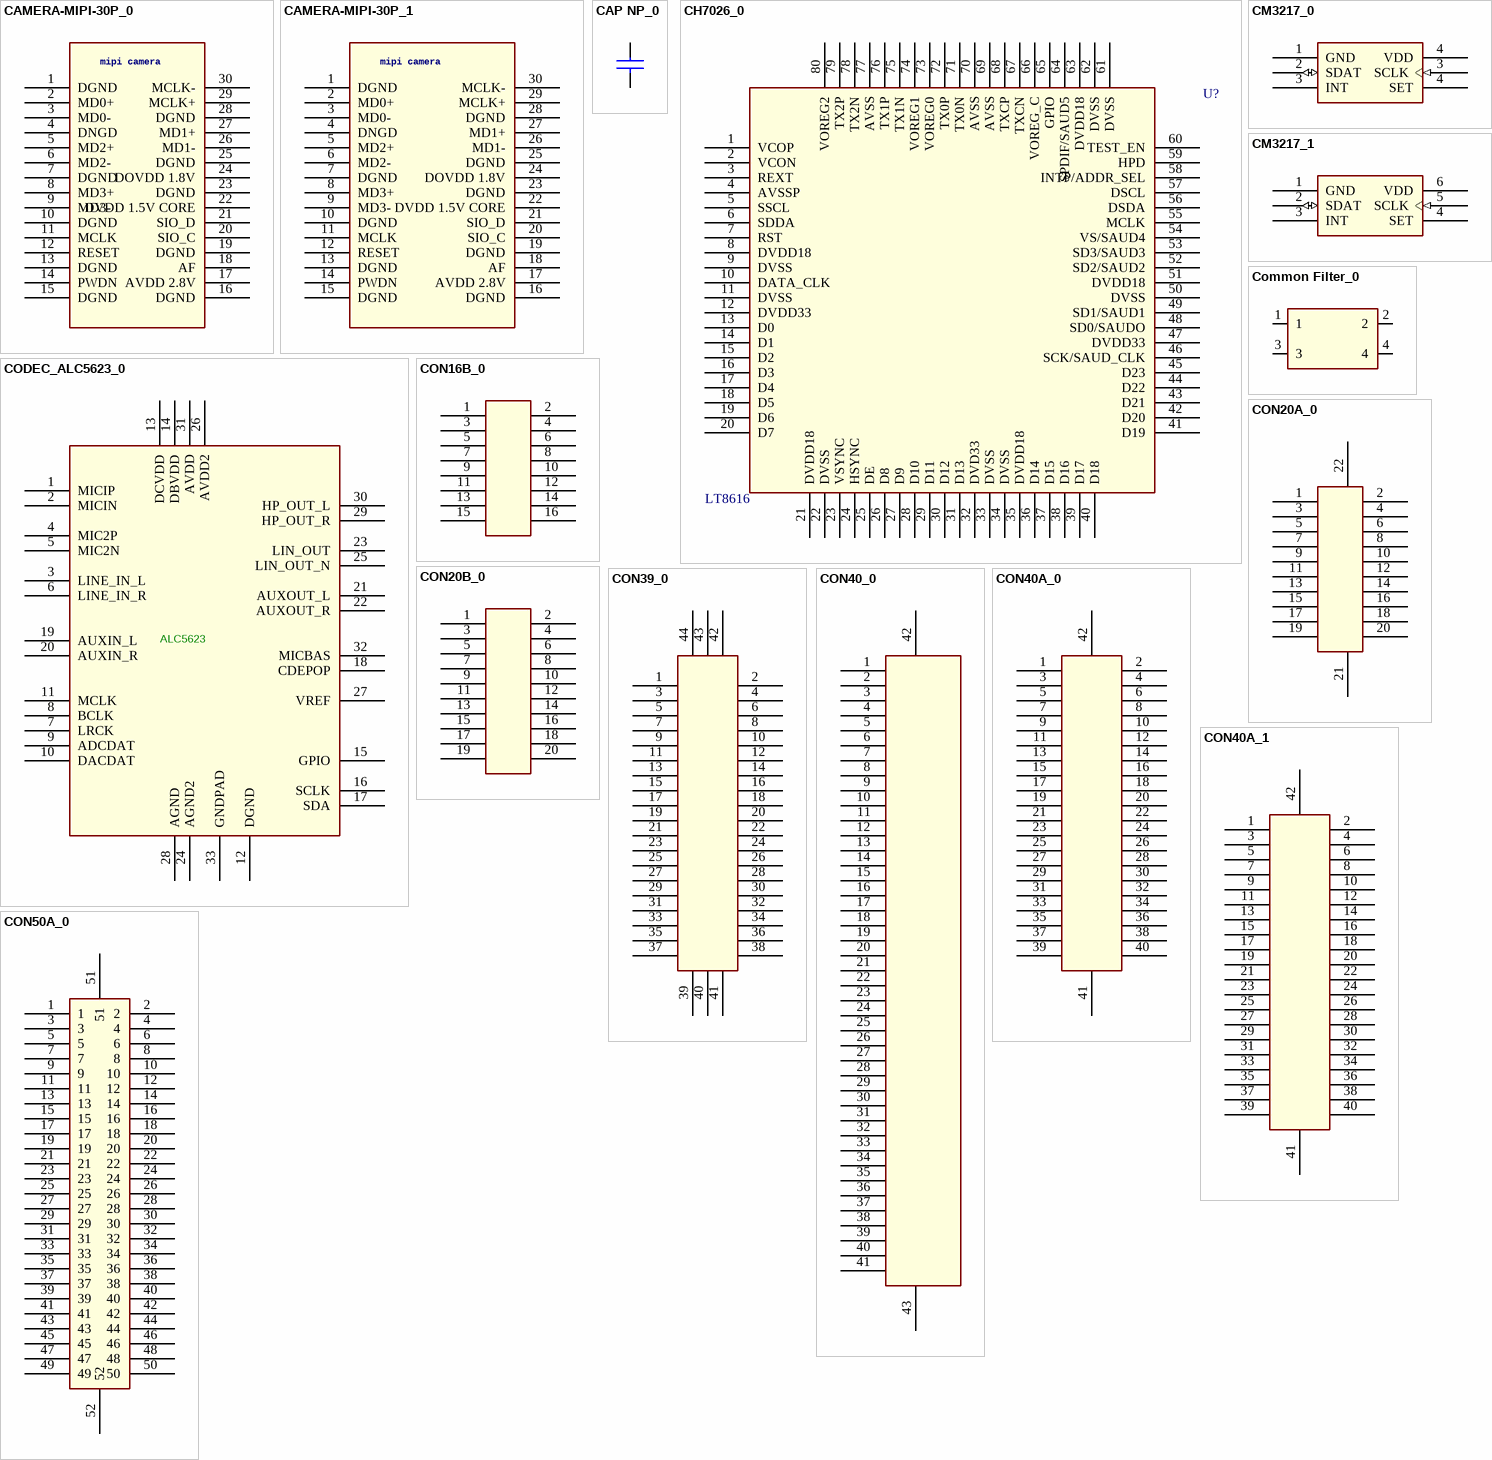
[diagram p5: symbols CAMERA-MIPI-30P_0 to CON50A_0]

## CAMERA-MIPI-30P_0
designator U?
Altium-Right: 90; Altium-Bottom: 190
pins: 1 DGND, 2 MD0+, 3 MD0-, 4 DNGD, 5 MD2+, 6 MD2-, 7 DGND, 8 MD3+, 9 MD3-, 10 DGND, 11 MCLK, 12 RESET, 13 DGND, 14 PWDN, 15 DGND, 16 DGND, 17 AVDD 2.8V, 18 AF, 19 DGND, 20 SIO_C, 21 SIO_D, 22 DVDD 1.5V CORE, 23 DGND, 24 DOVDD 1.8V, 25 DGND, 26 MD1-, 27 MD1+, 28 DGND, 29 MCLK+, 30 MCLK-

## CAMERA-MIPI-30P_1
designator U?
Altium-Right: 110; Altium-Bottom: 190
pins: 1 DGND, 2 MD0+, 3 MD0-, 4 DNGD, 5 MD2+, 6 MD2-, 7 DGND, 8 MD3+, 9 MD3-, 10 DGND, 11 MCLK, 12 RESET, 13 DGND, 14 PWDN, 15 DGND, 16 DGND, 17 AVDD 2.8V, 18 AF, 19 DGND, 20 SIO_C, 21 SIO_D, 22 DVDD 1.5V CORE, 23 DGND, 24 DOVDD 1.8V, 25 DGND, 26 MD1-, 27 MD1+, 28 DGND, 29 MCLK+, 30 MCLK-

## CAP NP_0
designator C?
Altium-Right: 20; Altium-Bottom: 10
pins: 1, 2

## CH7026_0
designator U?, comment LT8616
Altium-Right: 270
footprint LQFP80
pins: 1 VCOP, 2 VCON, 3 REXT, 4 AVSSP, 5 SSCL, 6 SDDA, 7 RST, 8 DVDD18 (power), 9 DVSS (power), 10 DATA_CLK, 11 DVSS (power), 12 DVDD33 (power), 13 D0, 14 D1, 15 D2, 16 D3, 17 D4, 18 D5, 19 D6, 20 D7, 21 DVDD18 (power), 22 DVSS (power), 23 VSYNC, 24 HSYNC, 25 DE, 26 D8, 27 D9, 28 D10, 29 D11, 30 D12, 31 D13, 32 DVD33 (power), 33 DVSS (power), 34 DVSS (power), 35 DVDD18 (power), 36 D14, 37 D15, 38 D16, 39 D17, 40 D18, 41 D19, 42 D20, 43 D21, 44 D22, 45 D23, 46 SCK/SAUD_CLK, 47 DVDD33 (power), 48 SD0/SAUDO, 49 SD1/SAUD1, 50 DVSS (power), 51 DVDD18 (power), 52 SD2/SAUD2, 53 SD3/SAUD3, 54 VS/SAUD4, 55 MCLK, 56 DSDA, 57 DSCL, 58 INTP/ADDR_SEL, 59 HPD, 60 TEST_EN, 61 DVSS (power), 62 DVSS (power), 63 DVDD18 (power), 64 SPDIF/SAUD5, 65 GPIO, 66 VOREG_C, 67 TXCN, 68 TXCP, 69 AVSS (power), 70 AVSS (power), 71 TX0N, 72 TX0P, 73 VOREG0, 74 VOREG1, 75 TX1N, 76 TX1P, 77 AVSS (power), 78 TX2N, 79 TX2P, 80 VOREG2

## CM3217_0
designator U?
Altium-Right: 70; Altium-Bottom: 40
footprint CM3217
pins: 1 GND (power), 2 SDAT (io), 3 SCLK (in), 3 INT, 4 SET, 4 VDD (power)

## CM3217_1
designator U?
Altium-Right: 70; Altium-Bottom: 40
footprint CM3217
pins: 1 GND (power), 2 SDAT (io), 3 INT, 4 SET, 5 SCLK (in), 6 VDD (power)

## CODEC_ALC5623_0
designator U?, comment ALC5623
Altium-Right: 180; Altium-Bottom: 260
pins: 1 MICIP, 2 MICIN, 3 LINE_IN_L, 4 MIC2P, 5 MIC2N, 6 LINE_IN_R, 7 LRCK, 8 BCLK, 9 ADCDAT, 10 DACDAT, 11 MCLK, 12 DGND, 13 DCVDD, 14 DBVDD, 15 GPIO, 16 SCLK, 17 SDA, 18 CDEPOP, 19 AUXIN_L, 20 AUXIN_R, 21 AUXOUT_L, 22 AUXOUT_R, 23 LIN_OUT, 24 AGND2, 25 LIN_OUT_N, 26 AVDD2, 27 VREF, 28 AGND, 29 HP_OUT_R, 30 HP_OUT_L, 31 AVDD, 32 MICBAS, 33 GNDPAD

## Common Filter_0
designator L?
Altium-Right: 60; Altium-Bottom: 40
pins: 1, 2, 3, 4

## CON16B_0
designator J?
Altium-Right: 30; Altium-Bottom: 90
pins: 1, 2, 3, 4, 5, 6, 7, 8, 9, 10, 11, 12, 13, 14, 15, 16

## CON20A_0
designator J?
Altium-Right: 30; Altium-Bottom: 110
pins: 1, 2, 3, 4, 5, 6, 7, 8, 9, 10, 11, 12, 13, 14, 15, 16, 17, 18, 19, 20, 21, 22

## CON20B_0
designator J?
Altium-Right: 30; Altium-Bottom: 110
pins: 1, 2, 3, 4, 5, 6, 7, 8, 9, 10, 11, 12, 13, 14, 15, 16, 17, 18, 19, 20

## CON39_0
designator J?
Altium-Right: 40; Altium-Bottom: 210
pins: 1, 2, 3, 4, 5, 6, 7, 8, 9, 10, 11, 12, 13, 14, 15, 16, 17, 18, 19, 20, 21, 22, 23, 24, 25, 26, 27, 28, 29, 30, 31, 32, 33, 34, 35, 36, 37, 38, 39, 40, 41, 42, 43, 44

## CON40_0
designator J?
Altium-Right: 50; Altium-Bottom: 420
pins: 1, 2, 3, 4, 5, 6, 7, 8, 9, 10, 11, 12, 13, 14, 15, 16, 17, 18, 19, 20, 21, 22, 23, 24, 25, 26, 27, 28, 29, 30, 31, 32, 33, 34, 35, 36, 37, 38, 39, 40, 41, 42, 43

## CON40A_0
designator J?
Altium-Right: 40; Altium-Bottom: 210
pins: 1, 2, 3, 4, 5, 6, 7, 8, 9, 10, 11, 12, 13, 14, 15, 16, 17, 18, 19, 20, 21, 22, 23, 24, 25, 26, 27, 28, 29, 30, 31, 32, 33, 34, 35, 36, 37, 38, 39, 40, 41, 42

## CON40A_1
designator J?
Altium-Right: 40; Altium-Bottom: 210
pins: 1, 2, 3, 4, 5, 6, 7, 8, 9, 10, 11, 12, 13, 14, 15, 16, 17, 18, 19, 20, 21, 22, 23, 24, 25, 26, 27, 28, 29, 30, 31, 32, 33, 34, 35, 36, 37, 38, 39, 40, 41, 42

## CON50A_0
designator J?
Altium-Right: 40; Altium-Bottom: 260
footprint 25PIN-S2.54
pins: 1, 2, 3, 4, 5, 6, 7, 8, 9, 10, 11, 12, 13, 14, 15, 16, 17, 18, 19, 20, 21, 22, 23, 24, 25, 26, 27, 28, 29, 30, 31, 32, 33, 34, 35, 36, 37, 38, 39, 40, 41, 42, 43, 44, 45, 46, 47, 48, 49, 50, 51, 52

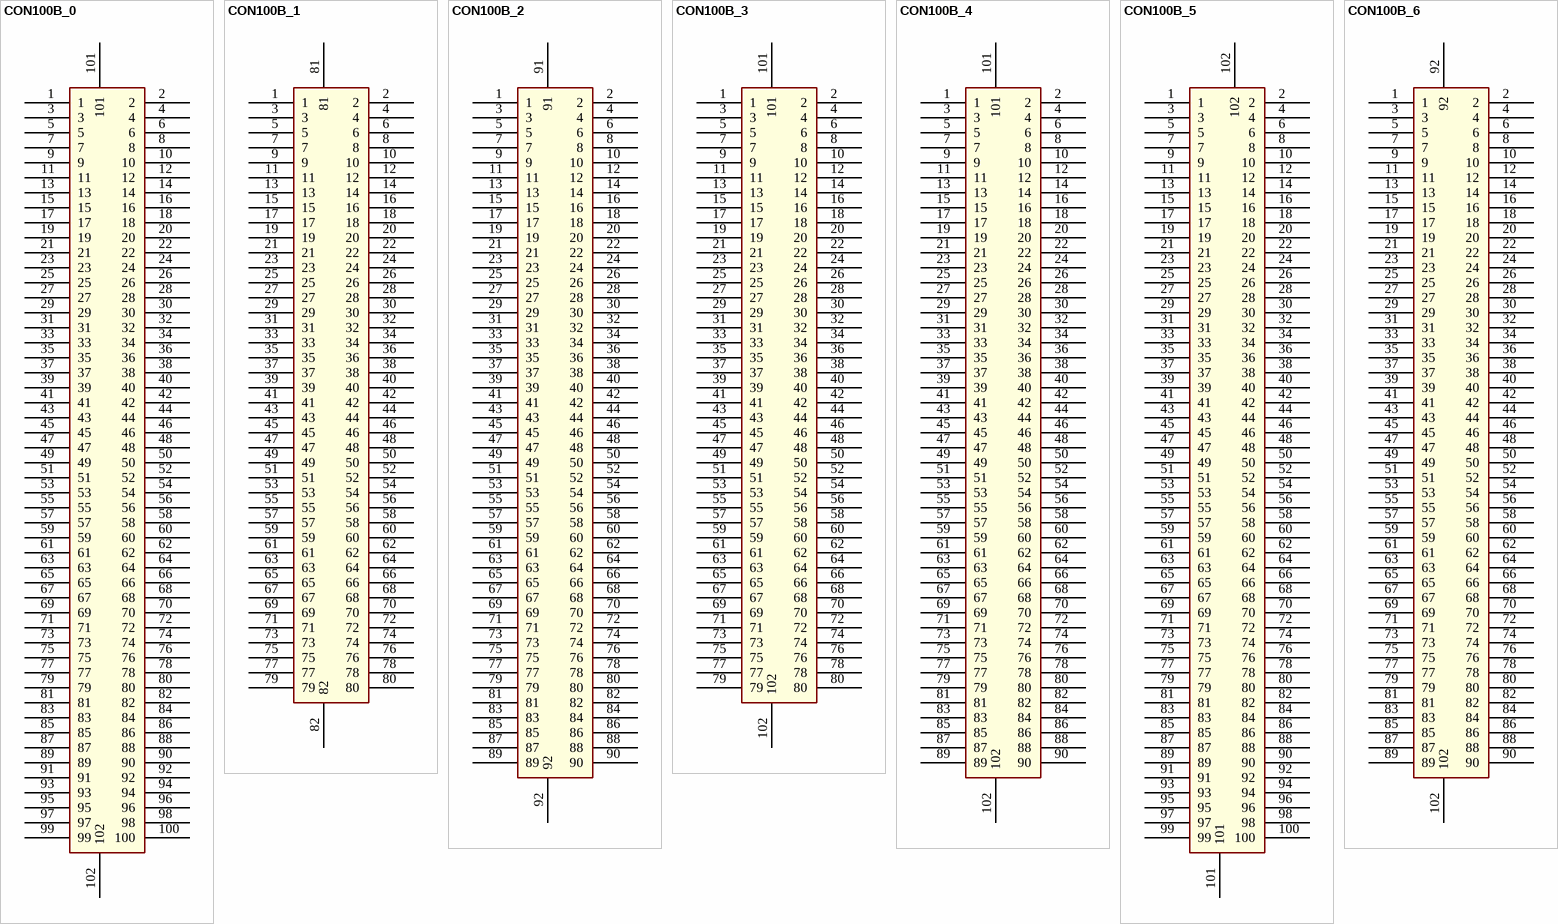
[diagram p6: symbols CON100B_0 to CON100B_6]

## CON100B_0
designator J?
Altium-Right: 50; Altium-Bottom: 510
footprint 50PIN-S1.27
pins: 1, 2, 3, 4, 5, 6, 7, 8, 9, 10, 11, 12, 13, 14, 15, 16, 17, 18, 19, 20, 21, 22, 23, 24, 25, 26, 27, 28, 29, 30, 31, 32, 33, 34, 35, 36, 37, 38, 39, 40, 41, 42, 43, 44, 45, 46, 47, 48, 49, 50, 51, 52, 53, 54, 55, 56, 57, 58, 59, 60, 61, 62, 63, 64, 65, 66, 67, 68, 69, 70, 71, 72, 73, 74, 75, 76, 77, 78, 79, 80, 81, 82, 83, 84, 85, 86, 87, 88, 89, 90, 91, 92, 93, 94, 95, 96, 97, 98, 99, 100, 101, 102

## CON100B_1
designator J?
Altium-Right: 50; Altium-Bottom: 410
footprint 50PIN-S1.27
pins: 1, 2, 3, 4, 5, 6, 7, 8, 9, 10, 11, 12, 13, 14, 15, 16, 17, 18, 19, 20, 21, 22, 23, 24, 25, 26, 27, 28, 29, 30, 31, 32, 33, 34, 35, 36, 37, 38, 39, 40, 41, 42, 43, 44, 45, 46, 47, 48, 49, 50, 51, 52, 53, 54, 55, 56, 57, 58, 59, 60, 61, 62, 63, 64, 65, 66, 67, 68, 69, 70, 71, 72, 73, 74, 75, 76, 77, 78, 79, 80, 81, 82

## CON100B_2
designator J?
Altium-Right: 50; Altium-Bottom: 460
footprint 50PIN-S1.27
pins: 1, 2, 3, 4, 5, 6, 7, 8, 9, 10, 11, 12, 13, 14, 15, 16, 17, 18, 19, 20, 21, 22, 23, 24, 25, 26, 27, 28, 29, 30, 31, 32, 33, 34, 35, 36, 37, 38, 39, 40, 41, 42, 43, 44, 45, 46, 47, 48, 49, 50, 51, 52, 53, 54, 55, 56, 57, 58, 59, 60, 61, 62, 63, 64, 65, 66, 67, 68, 69, 70, 71, 72, 73, 74, 75, 76, 77, 78, 79, 80, 81, 82, 83, 84, 85, 86, 87, 88, 89, 90, 91, 92

## CON100B_3
designator J?
Altium-Right: 50; Altium-Bottom: 410
footprint 50PIN-S1.27
pins: 1, 2, 3, 4, 5, 6, 7, 8, 9, 10, 11, 12, 13, 14, 15, 16, 17, 18, 19, 20, 21, 22, 23, 24, 25, 26, 27, 28, 29, 30, 31, 32, 33, 34, 35, 36, 37, 38, 39, 40, 41, 42, 43, 44, 45, 46, 47, 48, 49, 50, 51, 52, 53, 54, 55, 56, 57, 58, 59, 60, 61, 62, 63, 64, 65, 66, 67, 68, 69, 70, 71, 72, 73, 74, 75, 76, 77, 78, 79, 80, 101, 102

## CON100B_4
designator J?
Altium-Right: 50; Altium-Bottom: 460
footprint 50PIN-S1.27
pins: 1, 2, 3, 4, 5, 6, 7, 8, 9, 10, 11, 12, 13, 14, 15, 16, 17, 18, 19, 20, 21, 22, 23, 24, 25, 26, 27, 28, 29, 30, 31, 32, 33, 34, 35, 36, 37, 38, 39, 40, 41, 42, 43, 44, 45, 46, 47, 48, 49, 50, 51, 52, 53, 54, 55, 56, 57, 58, 59, 60, 61, 62, 63, 64, 65, 66, 67, 68, 69, 70, 71, 72, 73, 74, 75, 76, 77, 78, 79, 80, 81, 82, 83, 84, 85, 86, 87, 88, 89, 90, 101, 102

## CON100B_5
designator J?
Altium-Right: 50; Altium-Bottom: 510
footprint 50PIN-S1.27
pins: 1, 2, 3, 4, 5, 6, 7, 8, 9, 10, 11, 12, 13, 14, 15, 16, 17, 18, 19, 20, 21, 22, 23, 24, 25, 26, 27, 28, 29, 30, 31, 32, 33, 34, 35, 36, 37, 38, 39, 40, 41, 42, 43, 44, 45, 46, 47, 48, 49, 50, 51, 52, 53, 54, 55, 56, 57, 58, 59, 60, 61, 62, 63, 64, 65, 66, 67, 68, 69, 70, 71, 72, 73, 74, 75, 76, 77, 78, 79, 80, 81, 82, 83, 84, 85, 86, 87, 88, 89, 90, 91, 92, 93, 94, 95, 96, 97, 98, 99, 100, 101, 102

## CON100B_6
designator J?
Altium-Right: 50; Altium-Bottom: 460
footprint 50PIN-S1.27
pins: 1, 2, 3, 4, 5, 6, 7, 8, 9, 10, 11, 12, 13, 14, 15, 16, 17, 18, 19, 20, 21, 22, 23, 24, 25, 26, 27, 28, 29, 30, 31, 32, 33, 34, 35, 36, 37, 38, 39, 40, 41, 42, 43, 44, 45, 46, 47, 48, 49, 50, 51, 52, 53, 54, 55, 56, 57, 58, 59, 60, 61, 62, 63, 64, 65, 66, 67, 68, 69, 70, 71, 72, 73, 74, 75, 76, 77, 78, 79, 80, 81, 82, 83, 84, 85, 86, 87, 88, 89, 90, 92, 102

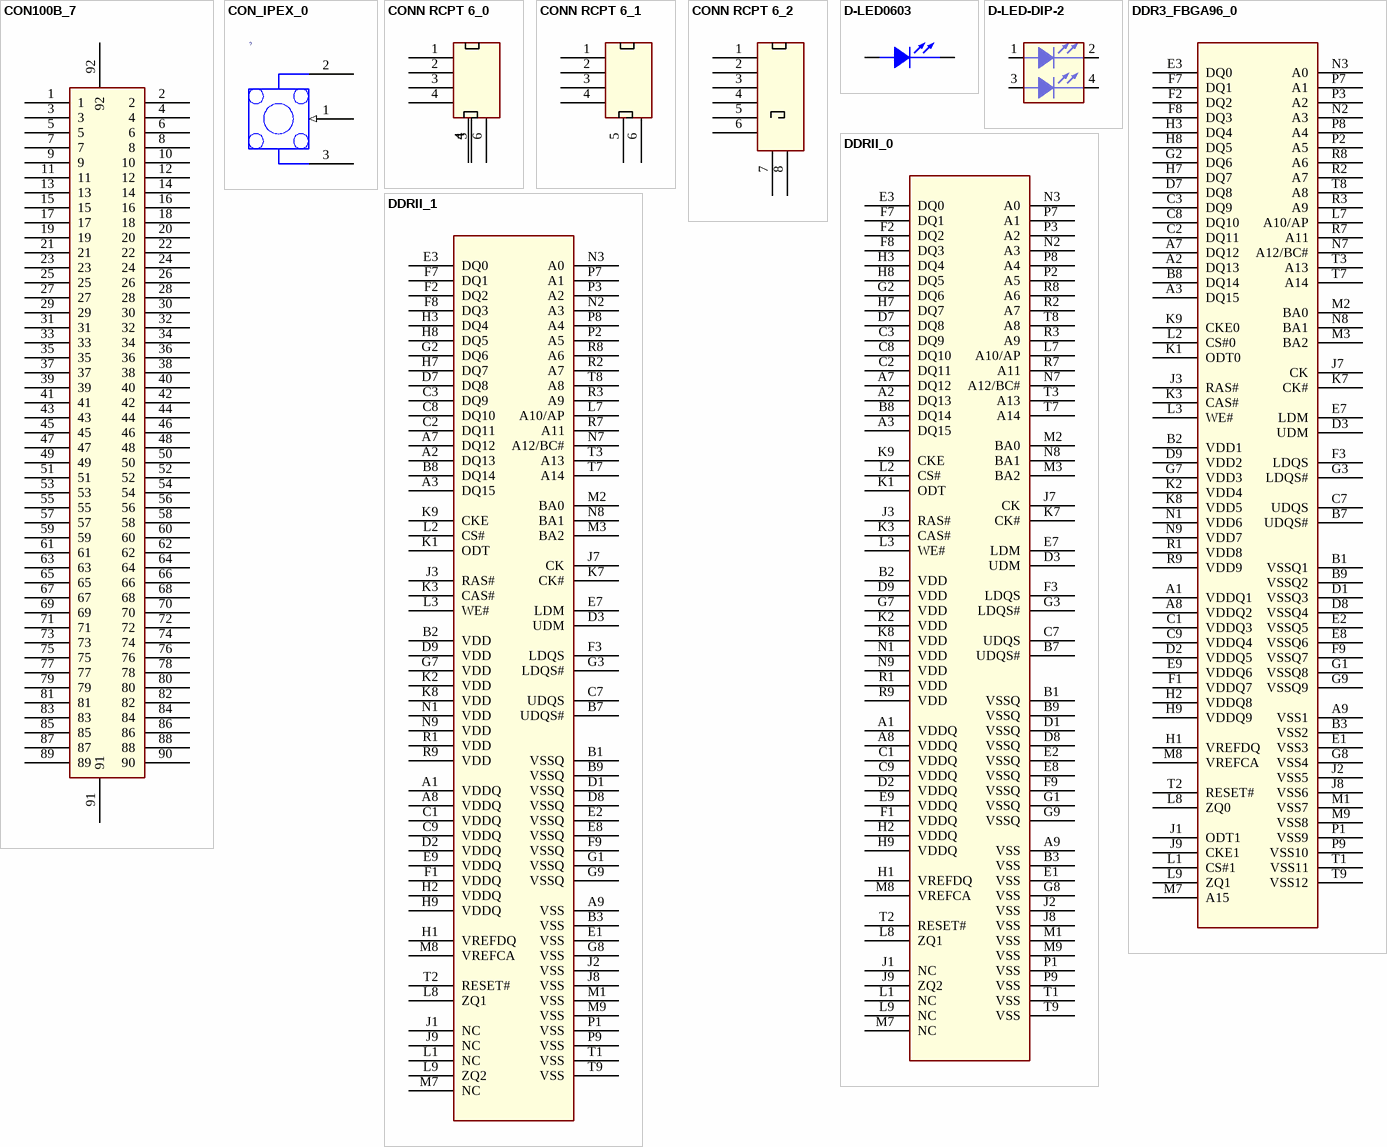
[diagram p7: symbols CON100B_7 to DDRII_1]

## CON100B_7
designator J?
Altium-Right: 50; Altium-Bottom: 460
footprint 50PIN-S1.27
pins: 1, 2, 3, 4, 5, 6, 7, 8, 9, 10, 11, 12, 13, 14, 15, 16, 17, 18, 19, 20, 21, 22, 23, 24, 25, 26, 27, 28, 29, 30, 31, 32, 33, 34, 35, 36, 37, 38, 39, 40, 41, 42, 43, 44, 45, 46, 47, 48, 49, 50, 51, 52, 53, 54, 55, 56, 57, 58, 59, 60, 61, 62, 63, 64, 65, 66, 67, 68, 69, 70, 71, 72, 73, 74, 75, 76, 77, 78, 79, 80, 81, 82, 83, 84, 85, 86, 87, 88, 89, 90, 91, 92

## CON_IPEX_0
designator ?, comment CON_IPEX  (value not drawn)
?; OriginalSymbolOrigin: (-100,200); Altium-Right: 40; Altium-Bottom: 80
pins: 1 IN (in), 2 GND1 (power), 3 GND2 (power)

## CONN RCPT 6_0
designator J?
Altium-Right: 31; Altium-Bottom: 50
pins: 1, 2, 3, 4, 4, 4, 4, 5, 6

## CONN RCPT 6_1
designator J?
Altium-Right: 31; Altium-Bottom: 50
pins: 1, 2, 3, 4, 5, 6

## CONN RCPT 6_2
designator J?
Altium-Right: 31; Altium-Bottom: 72
pins: 1, 2, 3, 4, 5, 6, 7, 8

## D-LED0603
designator LED?
Altium-Right: 40; Altium-Bottom: 20
pins: A ANODE, C CATHODE

## D-LED-DIP-2
designator LED?
Altium-Right: 40
pins: 1, 2, 3, 4

## DDR3_FBGA96_0
designator U?
Altium-Right: 80; Altium-Bottom: 590
footprint DDRII_X16
pins: A1 VDDQ1, A2 DQ13, A3 DQ15, A7 DQ12, A8 VDDQ2, A9 VSS1, B1 VSSQ1, B2 VDD1, B3 VSS2, B7 UDQS#, B8 DQ14, B9 VSSQ2, C1 VDDQ3, C2 DQ11, C3 DQ9, C7 UDQS, C8 DQ10, C9 VDDQ4, D1 VSSQ3, D2 VDDQ5, D3 UDM, D7 DQ8, D8 VSSQ4, D9 VDD2, E1 VSS3, E2 VSSQ5, E3 DQ0, E7 LDM, E8 VSSQ6, E9 VDDQ6, F1 VDDQ7, F2 DQ2, F3 LDQS, F7 DQ1, F8 DQ3, F9 VSSQ7, G1 VSSQ8, G2 DQ6, G3 LDQS#, G7 VDD3, G8 VSS4, G9 VSSQ9, H1 VREFDQ, H2 VDDQ8, H3 DQ4, H7 DQ7, H8 DQ5, H9 VDDQ9, J1 ODT1, J2 VSS5, J3 RAS#, J7 CK, J8 VSS6, J9 CKE1, K1 ODT0, K2 VDD4, K3 CAS#, K7 CK#, K8 VDD5, K9 CKE0, L1 CS#1, L2 CS#0, L3 WE#, L7 A10/AP, L8 ZQ0, L9 ZQ1, M1 VSS7, M2 BA0, M3 BA2, M7 A15, M8 VREFCA, M9 VSS8, N1 VDD6, N2 A3, N3 A0, N7 A12/BC#, N8 BA1, N9 VDD7, P1 VSS9, P2 A5, P3 A2, P7 A1, P8 A4, P9 VSS10, R1 VDD8, R2 A7, R3 A9, R7 A11, R8 A6, R9 VDD9, T1 VSS11, T2 RESET#, T3 A13, T7 A14, T8 A8, T9 VSS12

## DDRII_0
designator U?
Altium-Right: 80; Altium-Bottom: 590
footprint DDRII_X16
pins: A1 VDDQ, A2 DQ13, A3 DQ15, A7 DQ12, A8 VDDQ, A9 VSS, B1 VSSQ, B2 VDD, B3 VSS, B7 UDQS#, B8 DQ14, B9 VSSQ, C1 VDDQ, C2 DQ11, C3 DQ9, C7 UDQS, C8 DQ10, C9 VDDQ, D1 VSSQ, D2 VDDQ, D3 UDM, D7 DQ8, D8 VSSQ, D9 VDD, E1 VSS, E2 VSSQ, E3 DQ0, E7 LDM, E8 VSSQ, E9 VDDQ, F1 VDDQ, F2 DQ2, F3 LDQS, F7 DQ1, F8 DQ3, F9 VSSQ, G1 VSSQ, G2 DQ6, G3 LDQS#, G7 VDD, G8 VSS, G9 VSSQ, H1 VREFDQ, H2 VDDQ, H3 DQ4, H7 DQ7, H8 DQ5, H9 VDDQ, J1 NC, J2 VSS, J3 RAS#, J7 CK, J8 VSS, J9 ZQ2, K1 ODT, K2 VDD, K3 CAS#, K7 CK#, K8 VDD, K9 CKE, L1 NC, L2 CS#, L3 WE#, L7 A10/AP, L8 ZQ1, L9 NC, M1 VSS, M2 BA0, M3 BA2, M7 NC, M8 VREFCA, M9 VSS, N1 VDD, N2 A3, N3 A0, N7 A12/BC#, N8 BA1, N9 VDD, P1 VSS, P2 A5, P3 A2, P7 A1, P8 A4, P9 VSS, R1 VDD, R2 A7, R3 A9, R7 A11, R8 A6, R9 VDD, T1 VSS, T2 RESET#, T3 A13, T7 A14, T8 A8, T9 VSS

## DDRII_1
designator U?
Altium-Right: 80; Altium-Bottom: 590
footprint DDRII_X16
pins: A1 VDDQ, A2 DQ13, A3 DQ15, A7 DQ12, A8 VDDQ, A9 VSS, B1 VSSQ, B2 VDD, B3 VSS, B7 UDQS#, B8 DQ14, B9 VSSQ, C1 VDDQ, C2 DQ11, C3 DQ9, C7 UDQS, C8 DQ10, C9 VDDQ, D1 VSSQ, D2 VDDQ, D3 UDM, D7 DQ8, D8 VSSQ, D9 VDD, E1 VSS, E2 VSSQ, E3 DQ0, E7 LDM, E8 VSSQ, E9 VDDQ, F1 VDDQ, F2 DQ2, F3 LDQS, F7 DQ1, F8 DQ3, F9 VSSQ, G1 VSSQ, G2 DQ6, G3 LDQS#, G7 VDD, G8 VSS, G9 VSSQ, H1 VREFDQ, H2 VDDQ, H3 DQ4, H7 DQ7, H8 DQ5, H9 VDDQ, J1 NC, J2 VSS, J3 RAS#, J7 CK, J8 VSS, J9 NC, K1 ODT, K2 VDD, K3 CAS#, K7 CK#, K8 VDD, K9 CKE, L1 NC, L2 CS#, L3 WE#, L7 A10/AP, L8 ZQ1, L9 ZQ2, M1 VSS, M2 BA0, M3 BA2, M7 NC, M8 VREFCA, M9 VSS, N1 VDD, N2 A3, N3 A0, N7 A12/BC#, N8 BA1, N9 VDD, P1 VSS, P2 A5, P3 A2, P7 A1, P8 A4, P9 VSS, R1 VDD, R2 A7, R3 A9, R7 A11, R8 A6, R9 VDD, T1 VSS, T2 RESET#, T3 A13, T7 A14, T8 A8, T9 VSS

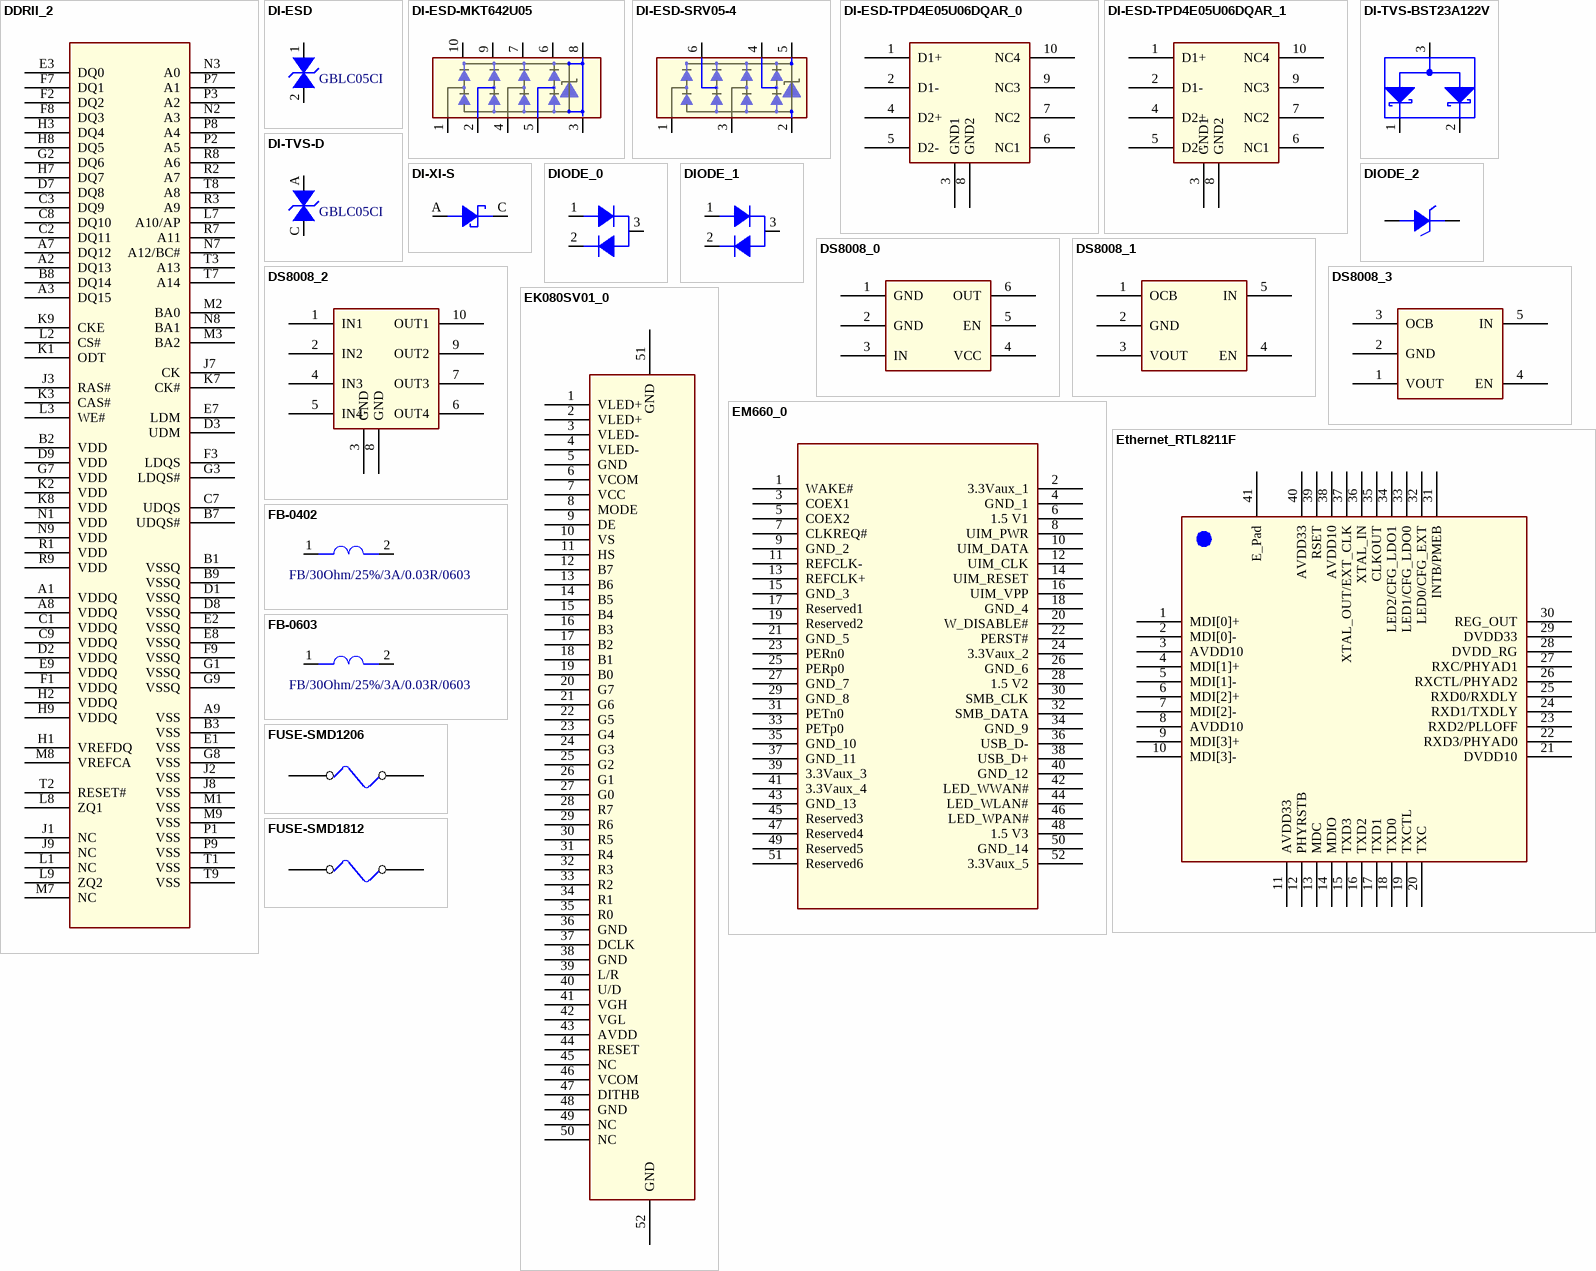
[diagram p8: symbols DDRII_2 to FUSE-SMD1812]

## DDRII_2
designator U?
Altium-Right: 80; Altium-Bottom: 590
footprint DDRII_X16
pins: A1 VDDQ, A2 DQ13, A3 DQ15, A7 DQ12, A8 VDDQ, A9 VSS, B1 VSSQ, B2 VDD, B3 VSS, B7 UDQS#, B8 DQ14, B9 VSSQ, C1 VDDQ, C2 DQ11, C3 DQ9, C7 UDQS, C8 DQ10, C9 VDDQ, D1 VSSQ, D2 VDDQ, D3 UDM, D7 DQ8, D8 VSSQ, D9 VDD, E1 VSS, E2 VSSQ, E3 DQ0, E7 LDM, E8 VSSQ, E9 VDDQ, F1 VDDQ, F2 DQ2, F3 LDQS, F7 DQ1, F8 DQ3, F9 VSSQ, G1 VSSQ, G2 DQ6, G3 LDQS#, G7 VDD, G8 VSS, G9 VSSQ, H1 VREFDQ, H2 VDDQ, H3 DQ4, H7 DQ7, H8 DQ5, H9 VDDQ, J1 NC, J2 VSS, J3 RAS#, J7 CK, J8 VSS, J9 NC, K1 ODT, K2 VDD, K3 CAS#, K7 CK#, K8 VDD, K9 CKE, L1 NC, L2 CS#, L3 WE#, L7 A10/AP, L8 ZQ1, L9 ZQ2, M1 VSS, M2 BA0, M3 BA2, M7 NC, M8 VREFCA, M9 VSS, N1 VDD, N2 A3, N3 A0, N7 A12/BC#, N8 BA1, N9 VDD, P1 VSS, P2 A5, P3 A2, P7 A1, P8 A4, P9 VSS, R1 VDD, R2 A7, R3 A9, R7 A11, R8 A6, R9 VDD, T1 VSS, T2 RESET#, T3 A13, T7 A14, T8 A8, T9 VSS

## DI-ESD
designator T?, comment GBLC05CI
ESD 0402; Part Number: EB3.1R0UV18402A; Manufacture P/N: MLVG04021R0UV18; Manufacturer: INPAQ; PN Type: Varistor; Altium-Right: 20
pins: 1 I/O2, 2 I/O1

## DI-ESD-MKT642U05
designator D?
Altium-Right: 112; Altium-Bottom: 40
pins: 1, 2, 3, 4, 5, 6, 7, 8, 9, 10

## DI-ESD-SRV05-4
designator D?
Altium-Right: 100; Altium-Bottom: 40
pins: 1, 2, 3, 4, 5, 6

## DI-ESD-TPD4E05U06DQAR_0
designator U?
Altium-Right: 80
pins: 1 D1+, 2 D1-, 3 GND1, 4 D2+, 5 D2-, 6 NC1, 7 NC2, 8 GND2, 9 NC3, 10 NC4

## DI-ESD-TPD4E05U06DQAR_1
designator U?
Altium-Right: 70; Altium-Bottom: 80
pins: 1 D1+, 2 D1-, 3 GND1, 4 D2+, 5 D2-, 6 NC1, 7 NC2, 8 GND2, 9 NC3, 10 NC4

## DI-TVS-BST23A122V
designator D?
Altium-Right: 60; Altium-Bottom: 40
pins: 1, 2, 3

## DI-TVS-D
designator T?, comment GBLC05CI
ESD 0402; Part Number: EB3.1R0UV18402A; Manufacture P/N: MLVG04021R0UV18; Manufacturer: INPAQ; PN Type: Varistor; Altium-Right: 20
pins: A I/O2, C I/O1

## DI-XI-S
designator D?
CLASS: IC; Altium-Right: 30; Altium-Bottom: 20
pins: A, C

## DIODE_0
designator D?
Altium-Right: 30; Altium-Bottom: 40
pins: 1 ANODE, 2 CATHODE, 3 COMMON

## DIODE_1
designator D?
Altium-Right: 30; Altium-Bottom: 40
pins: 1 ANODE, 2 CATHODE, 3 COMMON

## DIODE_2
designator D?
Altium-Right: 30; Altium-Bottom: 20
pins: 1 A, 2 K

## DS8008_0
designator U?
Altium-Right: 70; Altium-Bottom: 60
pins: 1 GND, 2 GND, 3 IN, 4 VCC, 5 EN, 6 OUT

## DS8008_1
designator U?
Altium-Right: 70; Altium-Bottom: 60
pins: 1 OCB, 2 GND, 3 VOUT, 4 EN, 5 IN

## DS8008_2
designator U?
Altium-Right: 70; Altium-Bottom: 80
pins: 1 IN1, 2 IN2, 3 GND (power), 4 IN3, 5 IN4, 6 OUT4, 7 OUT3, 8 GND, 9 OUT2, 10 OUT1

## DS8008_3
designator U?
Altium-Right: 70; Altium-Bottom: 60
pins: 1 VOUT, 2 GND, 3 OCB, 4 EN, 5 IN

## EK080SV01_0
designator J?
Altium-Right: 70; Altium-Bottom: 550
pins: 1 VLED+, 2 VLED+, 3 VLED-, 4 VLED-, 5 GND, 6 VCOM, 7 VCC, 8 MODE, 9 DE, 10 VS, 11 HS, 12 B7, 13 B6, 14 B5, 15 B4, 16 B3, 17 B2, 18 B1, 19 B0, 20 G7, 21 G6, 22 G5, 23 G4, 24 G3, 25 G2, 26 G1, 27 G0, 28 R7, 29 R6, 30 R5, 31 R4, 32 R3, 33 R2, 34 R1, 35 R0, 36 GND, 37 DCLK, 38 GND, 39 L/R, 40 U/D, 41 VGH, 42 VGL, 43 AVDD, 44 RESET, 45 NC, 46 VCOM, 47 DITHB, 48 GND, 49 NC, 50 NC, 51 GND, 52 GND

## EM660_0
designator U?
Altium-Right: 160; Altium-Bottom: 310
pins: 1 WAKE#, 2 3.3Vaux_1 (power), 3 COEX1, 4 GND_1 (power), 5 COEX2, 6 1.5 V1, 7 CLKREQ#, 8 UIM_PWR, 9 GND_2 (power), 10 UIM_DATA, 11 REFCLK-, 12 UIM_CLK, 13 REFCLK+, 14 UIM_RESET, 15 GND_3 (power), 16 UIM_VPP, 17 Reserved1, 18 GND_4 (power), 19 Reserved2, 20 W_DISABLE#, 21 GND_5 (power), 22 PERST#, 23 PERn0, 24 3.3Vaux_2 (power), 25 PERp0, 26 GND_6 (power), 27 GND_7 (power), 28 1.5 V2, 29 GND_8 (power), 30 SMB_CLK, 31 PETn0, 32 SMB_DATA, 33 PETp0, 34 GND_9 (power), 35 GND_10 (power), 36 USB_D-, 37 GND_11 (power), 38 USB_D+, 39 3.3Vaux_3 (power), 40 GND_12, 41 3.3Vaux_4 (power), 42 LED_WWAN#, 43 GND_13 (power), 44 LED_WLAN#, 45 Reserved3, 46 LED_WPAN#, 47 Reserved4, 48 1.5 V3, 49 Reserved5, 50 GND_14 (power), 51 Reserved6, 52 3.3Vaux_5 (power)

## Ethernet_RTL8211F
designator U?
Altium-Right: 230
footprint QFN40_5R00X5R00X0R80_T
pins: 1 MDI[0]+, 2 MDI[0]-, 3 AVDD10 (power), 4 MDI[1]+, 5 MDI[1]-, 6 MDI[2]+, 7 MDI[2]-, 8 AVDD10 (power), 9 MDI[3]+, 10 MDI[3]-, 11 AVDD33 (power), 12 PHYRSTB, 13 MDC, 14 MDIO, 15 TXD3, 16 TXD2, 17 TXD1, 18 TXD0, 19 TXCTL, 20 TXC, 21 DVDD10 (power), 22 RXD3/PHYAD0, 23 RXD2/PLLOFF, 24 RXD1/TXDLY, 25 RXD0/RXDLY, 26 RXCTL/PHYAD2, 27 RXC/PHYAD1, 28 DVDD_RG, 29 DVDD33 (power), 30 REG_OUT, 31 INTB/PMEB, 32 LED0/CFG_EXT, 33 LED1/CFG_LDO0, 34 LED2/CFG_LDO1, 35 CLKOUT, 36 XTAL_IN, 37 XTAL_OUT/EXT_CLK, 38 AVDD10 (power), 39 RSET, 40 AVDD33 (power), 41 E_Pad

## FB-0402
designator FB?, comment FB/30Ohm/25%/3A/0.03R/0603
SMD Multilayer Ferrite Chip Bead,3A,30Ohm,0.03R; Part Number: EL4.300Y060300A; Manufacture P/N: PZ1608D300-3R0TF; Manufacture2 P/N: PBY160808T-400Y-N; Manufacturer: SUNLORD; PN Type: SMD FERRITE BEAD; Altium-Right: 40; Altium-Bottom: 20
pins: 1, 2

## FB-0603
designator FB?, comment FB/30Ohm/25%/3A/0.03R/0603
SMD Multilayer Ferrite Chip Bead,3A,30Ohm,0.03R; Part Number: EL4.300Y060300A; Manufacture P/N: PZ1608D300-3R0TF; Manufacture2 P/N: PBY160808T-400Y-N; Manufacturer: SUNLORD; PN Type: SMD FERRITE BEAD; Altium-Right: 40; Altium-Bottom: 20
pins: 1, 2

## FUSE-SMD1206
designator F?
Altium-Right: 30; Altium-Bottom: 20
pins: 1, 2

## FUSE-SMD1812
designator F?
Altium-Right: 30; Altium-Bottom: 20
pins: 1, 2

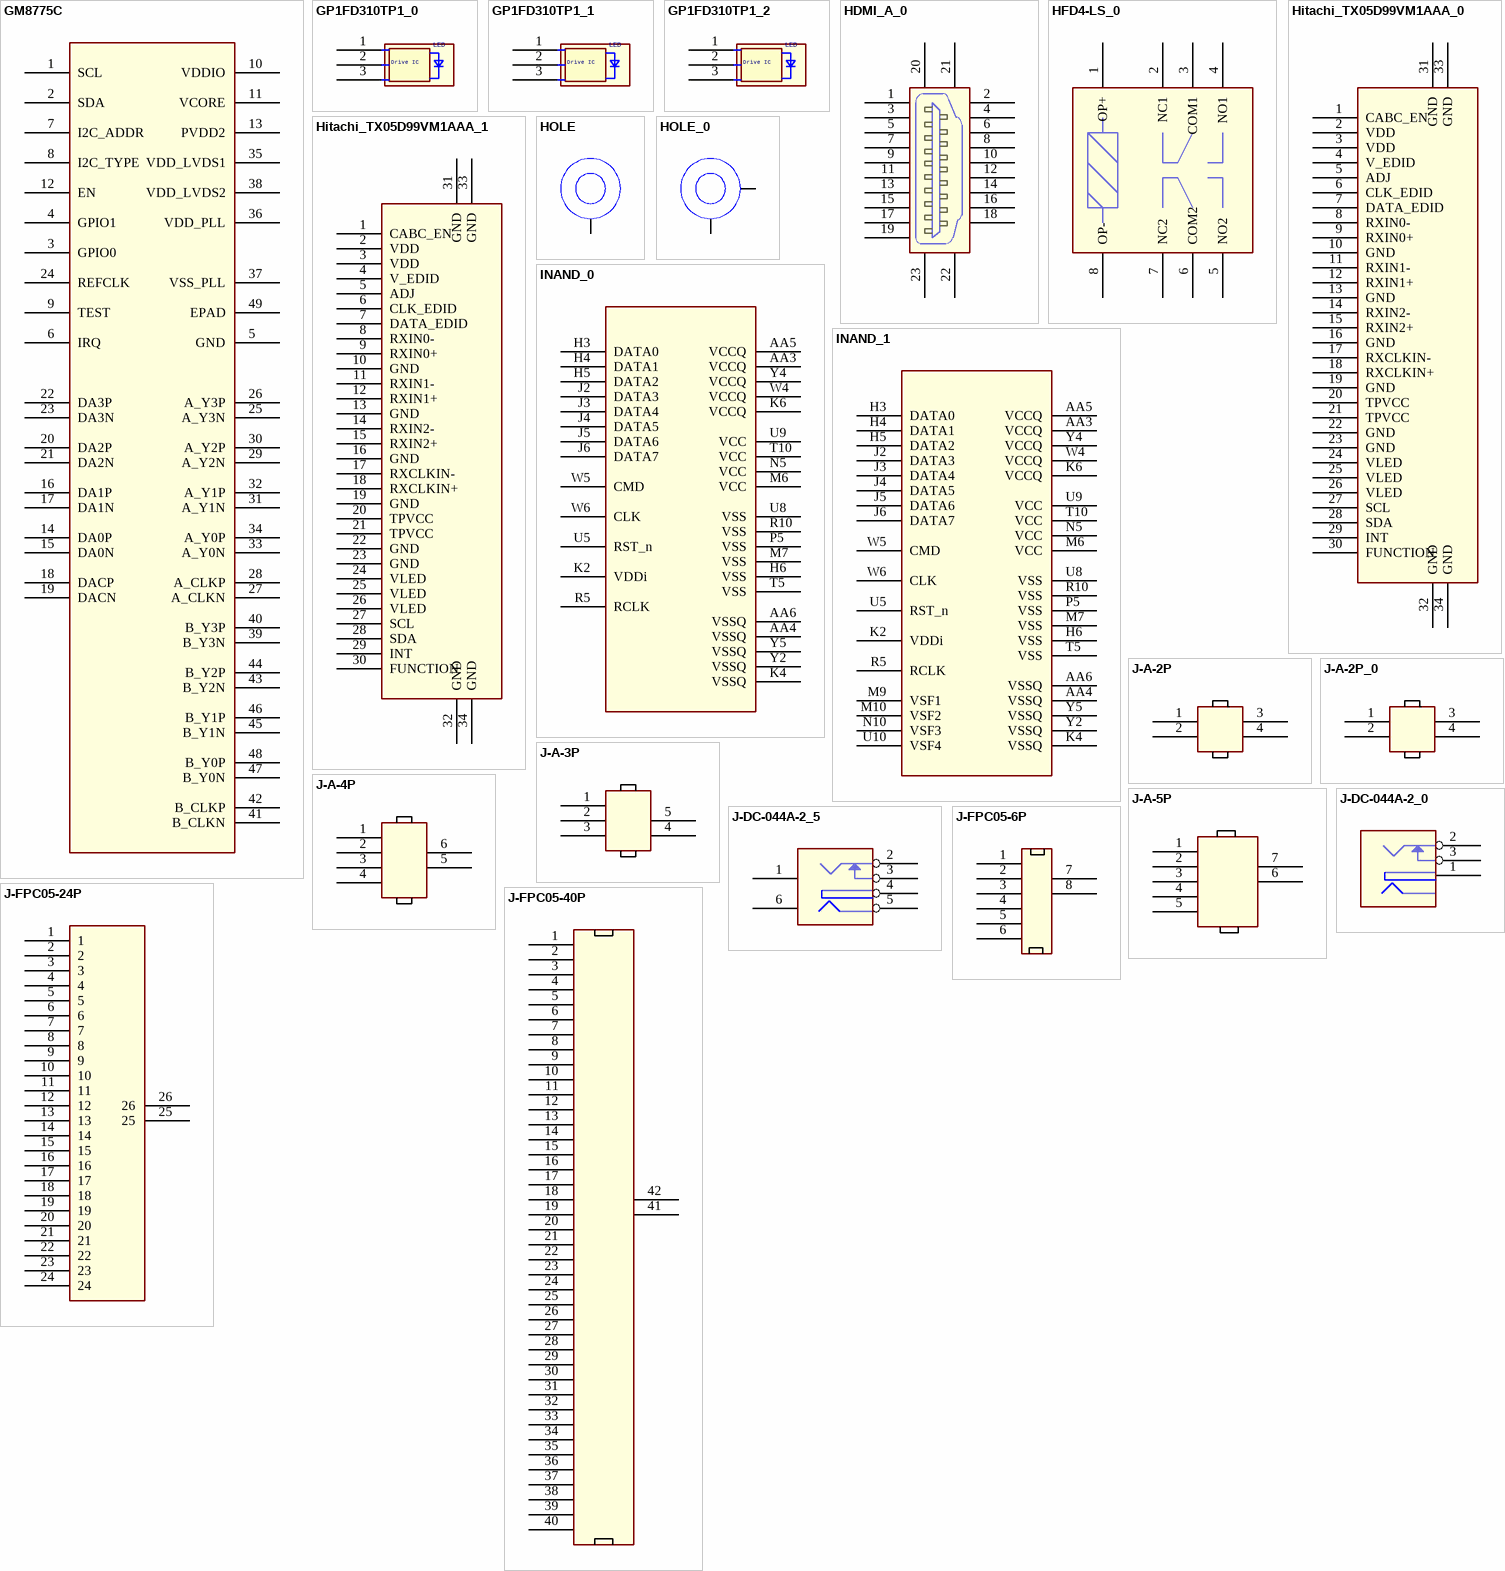
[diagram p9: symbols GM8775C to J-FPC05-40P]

## GM8775C
designator U?
Altium-Right: 110; Altium-Bottom: 540
pins: 1 SCL, 2 SDA, 3 GPIO0, 4 GPIO1, 5 GND, 6 IRQ, 7 I2C_ADDR, 8 I2C_TYPE, 9 TEST, 10 VDDIO, 11 VCORE, 12 EN, 13 PVDD2, 14 DA0P, 15 DA0N, 16 DA1P, 17 DA1N, 18 DACP, 19 DACN, 20 DA2P, 21 DA2N, 22 DA3P, 23 DA3N, 24 REFCLK, 25 A_Y3N, 26 A_Y3P, 27 A_CLKN, 28 A_CLKP, 29 A_Y2N, 30 A_Y2P, 31 A_Y1N, 32 A_Y1P, 33 A_Y0N, 34 A_Y0P, 35 VDD_LVDS1, 36 VDD_PLL, 37 VSS_PLL, 38 VDD_LVDS2, 39 B_Y3N, 40 B_Y3P, 41 B_CLKN, 42 B_CLKP, 43 B_Y2N, 44 B_Y2P, 45 B_Y1N, 46 B_Y1P, 47 B_Y0N, 48 B_Y0P, 49 EPAD

## GP1FD310TP1_0
designator U?
Altium-Right: 50; Altium-Bottom: 40
pins: 1 GND, 2 Vcc, 3 VIN

## GP1FD310TP1_1
designator U?
Altium-Right: 50; Altium-Bottom: 40
pins: 1 GND, 2 Vcc, 3 VIN

## GP1FD310TP1_2
designator U?
Altium-Right: 50; Altium-Bottom: 40
pins: 1 GND, 2 Vcc, 3 VIN

## HDMI_A_0
designator J?
Altium-Right: 40; Altium-Bottom: 110
pins: 1 $PIN0, 2, 3, 4, 5, 6, 7, 8, 9, 10, 11, 12, 13, 14, 15, 16, 17, 18, 19, 20, 21, 22, 23

## HFD4-LS_0
designator M?
Altium-Right: 120; Altium-Bottom: 110
pins: 1 OP+, 2 NC1, 3 COM1, 4 NO1, 5 NO2, 6 COM2, 7 NC2, 8 OP-

## Hitachi_TX05D99VM1AAA_0
designator CON?
Altium-Right: 80; Altium-Bottom: 330
pins: 1 CABC_EN, 2 VDD, 3 VDD, 4 V_EDID, 5 ADJ, 6 CLK_EDID, 7 DATA_EDID, 8 RXIN0-, 9 RXIN0+, 10 GND, 11 RXIN1-, 12 RXIN1+, 13 GND, 14 RXIN2-, 15 RXIN2+, 16 GND, 17 RXCLKIN-, 18 RXCLKIN+, 19 GND, 20 TPVCC, 21 TPVCC, 22 GND, 23 GND, 24 VLED, 25 VLED, 26 VLED, 27 SCL, 28 SDA, 29 INT, 30 FUNCTION, 31 GND, 32 GND, 33 GND, 34 GND

## Hitachi_TX05D99VM1AAA_1
designator CON?
Altium-Right: 80; Altium-Bottom: 330
pins: 1 CABC_EN, 2 VDD, 3 VDD, 4 V_EDID, 5 ADJ, 6 CLK_EDID, 7 DATA_EDID, 8 RXIN0-, 9 RXIN0+, 10 GND, 11 RXIN1-, 12 RXIN1+, 13 GND, 14 RXIN2-, 15 RXIN2+, 16 GND, 17 RXCLKIN-, 18 RXCLKIN+, 19 GND, 20 TPVCC, 21 TPVCC, 22 GND, 23 GND, 24 VLED, 25 VLED, 26 VLED, 27 SCL, 28 SDA, 29 INT, 30 FUNCTION, 31 GND, 32 GND, 33 GND, 34 GND

## HOLE
designator H?  (value not drawn)
Altium-Right: 40
pins: 1

## HOLE_0
designator H?  (value not drawn)
Altium-Right: 40
pins: 1, 2

## INAND_0
designator U?
Altium-Right: 100; Altium-Bottom: 270
footprint INANA-BGA169
pins: AA3 VCCQ (power), AA4 VSSQ (power), AA5 VCCQ (power), AA6 VSSQ (power), H3 DATA0, H4 DATA1, H5 DATA2, H6 VSS (power), J2 DATA3, J3 DATA4, J4 DATA5, J5 DATA6, J6 DATA7, K2 VDDi, K4 VSSQ (power), K6 VCCQ (power), M6 VCC (power), M7 VSS (power), N5 VCC (power), P5 VSS (power), R5 RCLK, R10 VSS (power), T5 VSS (power), T10 VCC (power), U5 RST_n, U8 VSS (power), U9 VCC (power), W4 VCCQ (power), W5 CMD, W6 CLK, Y2 VSSQ (power), Y4 VCCQ (power), Y5 VSSQ (power)

## INAND_1
designator U?
Altium-Right: 100; Altium-Bottom: 270
footprint INANA-BGA169
pins: AA3 VCCQ (power), AA4 VSSQ (power), AA5 VCCQ (power), AA6 VSSQ (power), H3 DATA0, H4 DATA1, H5 DATA2, H6 VSS (power), J2 DATA3, J3 DATA4, J4 DATA5, J5 DATA6, J6 DATA7, K2 VDDi, K4 VSSQ (power), K6 VCCQ (power), M6 VCC (power), M7 VSS (power), M9 VSF1, M10 VSF2, N5 VCC (power), N10 VSF3, P5 VSS (power), R5 RCLK, R10 VSS (power), T5 VSS (power), T10 VCC (power), U5 RST_n, U8 VSS (power), U9 VCC (power), U10 VSF4, W4 VCCQ (power), W5 CMD, W6 CLK, Y2 VSSQ (power), Y4 VCCQ (power), Y5 VSSQ (power)

## J-A-2P
designator J?
Altium-Right: 30; Altium-Bottom: 50
pins: 1, 2, 3, 4

## J-A-2P_0
designator J?
Altium-Right: 30; Altium-Bottom: 50
pins: 1, 2, 3, 4

## J-A-3P
designator J?
Altium-Right: 30; Altium-Bottom: 60
pins: 1, 2, 3, 4, 5

## J-A-4P
designator J?
Altium-Right: 30; Altium-Bottom: 70
pins: 1, 2, 3, 4, 5, 6

## J-A-5P
designator J?
Altium-Right: 40; Altium-Bottom: 80
pins: 1 10, 2 8, 3 6, 4, 5 2, 6 9, 7

## J-DC-044A-2_0
designator J?
Altium-Right: 50; Altium-Bottom: 51
pins: 1, 2, 3

## J-DC-044A-2_5
designator J?
Altium-Right: 50; Altium-Bottom: 51
pins: 1, 2, 3, 4, 5, 6

## J-FPC05-6P
designator J?
Altium-Right: 20; Altium-Bottom: 70
pins: 1, 2, 3, 4, 5, 6, 7, 8

## J-FPC05-24P
designator J?
Altium-Right: 50; Altium-Bottom: 250
pins: 1, 2, 3, 4, 5, 6, 7, 8, 9, 10, 11, 12, 13, 14, 15, 16, 17, 18, 19, 20, 21, 22, 23, 24, 25, 26

## J-FPC05-40P
designator J?
Altium-Right: 40; Altium-Bottom: 410
pins: 1, 2, 3, 4, 5, 6, 7, 8, 9, 10, 11, 12, 13, 14, 15, 16, 17, 18, 19, 20, 21, 22, 23, 24, 25, 26, 27, 28, 29, 30, 31, 32, 33, 34, 35, 36, 37, 38, 39, 40, 41, 42

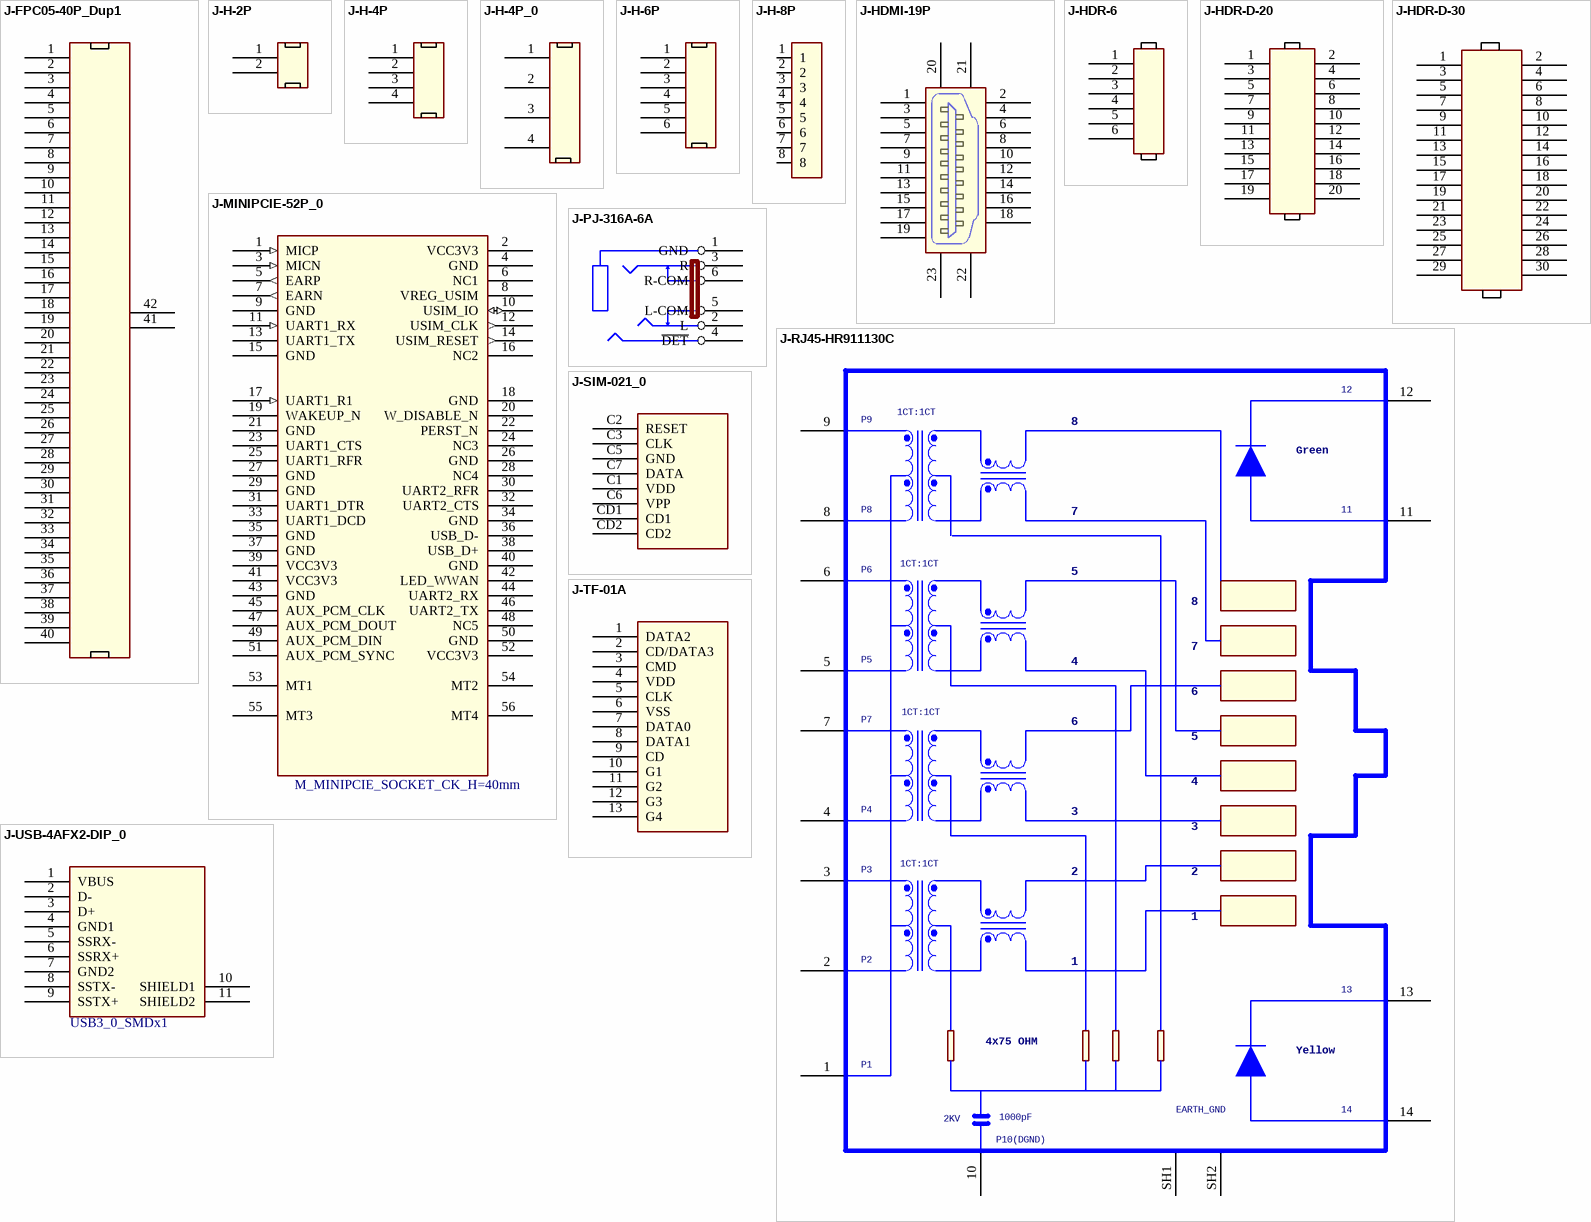
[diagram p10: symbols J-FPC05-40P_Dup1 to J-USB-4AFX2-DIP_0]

## J-FPC05-40P_Dup1
designator J?
Altium-Right: 40; Altium-Bottom: 410
pins: 1, 2, 3, 4, 5, 6, 7, 8, 9, 10, 11, 12, 13, 14, 15, 16, 17, 18, 19, 20, 21, 22, 23, 24, 25, 26, 27, 28, 29, 30, 31, 32, 33, 34, 35, 36, 37, 38, 39, 40, 41, 42

## J-H-2P
designator J?
Altium-Right: 20; Altium-Bottom: 30
pins: 1, 2

## J-H-4P
designator J?
Altium-Right: 20; Altium-Bottom: 50
pins: 1, 2, 3, 4

## J-H-4P_0
designator J?
Altium-Right: 20; Altium-Bottom: 80
pins: 1, 2, 3, 4

## J-H-6P
designator J?
Altium-Right: 20; Altium-Bottom: 70
pins: 1, 2, 3, 4, 5, 6

## J-H-8P
designator J?
Altium-Right: 20; Altium-Bottom: 90
pins: 1, 2, 3, 4, 5, 6, 7, 8

## J-HDMI-19P
designator J?
Altium-Right: 40; Altium-Bottom: 110
pins: 1 $PIN0, 2, 3, 4, 5, 6, 7, 8, 9, 10, 11, 12, 13, 14, 15, 16, 17, 18, 19, 20, 21, 22, 23

## J-HDR-6
designator J?
Altium-Right: 20; Altium-Bottom: 90
pins: 1, 2, 3, 4, 5, 6

## J-HDR-D-20
designator J?
Altium-Right: 30; Altium-Bottom: 130
pins: 1, 2, 3, 4, 5, 6, 7, 8, 9, 10, 11, 12, 13, 14, 15, 16, 17, 18, 19, 20

## J-HDR-D-30
designator J?
Altium-Right: 40; Altium-Bottom: 175
pins: 1, 2 16, 3 2, 4 17, 5 3, 6 18, 7 4, 8 19, 9 5, 10 20, 11 6, 12 21, 13 7, 14 22, 15 8, 16 23, 17 9, 18 24, 19 10, 20 25, 21 11, 22 26, 23 12, 24 27, 25 13, 26 28, 27 14, 28 29, 29 15, 30

## J-MINIPCIE-52P_0
designator MINI-PCIE?, comment M_MINIPCIE_SOCKET_CK_H=40mm
CLASS: IO; Altium-Right: 140; Altium-Bottom: 360
pins: 1 MICP (in), 2 VCC3V3 (power), 3 MICN (in), 4 GND (power), 5 EARP (out), 6 NC1, 7 EARN (out), 8 VREG_USIM (power), 9 GND (power), 10 USIM_IO (io), 11 UART1_RX (in), 12 USIM_CLK (out), 13 UART1_TX, 14 USIM_RESET (out), 15 GND (power), 16 NC2, 17 UART1_R1 (in), 18 GND (power), 19 WAKEUP_N, 20 W_DISABLE_N, 21 GND (power), 22 PERST_N, 23 UART1_CTS, 24 NC3, 25 UART1_RFR, 26 GND (power), 27 GND (power), 28 NC4, 29 GND (power), 30 UART2_RFR, 31 UART1_DTR, 32 UART2_CTS, 33 UART1_DCD, 34 GND (power), 35 GND (power), 36 USB_D-, 37 GND (power), 38 USB_D+, 39 VCC3V3 (power), 40 GND (power), 41 VCC3V3 (power), 42 LED_WWAN, 43 GND (power), 44 UART2_RX, 45 AUX_PCM_CLK, 46 UART2_TX, 47 AUX_PCM_DOUT, 48 NC5, 49 AUX_PCM_DIN, 50 GND (power), 51 AUX_PCM_SYNC, 52 VCC3V3 (power), 53 MT1, 54 MT2, 55 MT3, 56 MT4

## J-PJ-316A-6A
designator J?
Altium-Right: 80
pins: 1 GND, 2 L, 3 R, 4 ~{DET}, 5 L-COM, 6 R-COM

## J-RJ45-HR911130C
designator RJ45?
Altium-Right: 360; Altium-Bottom: 520
pins: 1 CT1/2/3/4, 2 MDI_0+, 3 MDI_0-, 4 MDI_1+, 5 MDI_2+, 6 MDI_2-, 7 MDI_1-, 8 MDI_3+, 9 MDI_3-, 10 GND, 11 G_LED+, 12 G_LED-, 13 Y_LED-, 14 Y_LED+, SH1, SH2

## J-SIM-021_0
designator J?
Altium-Right: 60; Altium-Bottom: 90
pins: C1 VDD, C2 RESET, C3 CLK, C5 GND, C6 VPP, C7 DATA, CD1, CD2

## J-TF-01A
designator J?
Altium-Right: 60; Altium-Bottom: 140
pins: 1 DATA2, 2 CD/DATA3, 3 CMD, 4 VDD, 5 CLK, 6 VSS, 7 DATA0, 8 DATA1, 9 CD, 10 G1, 11 G2, 12 G3, 13 G4

## J-USB-4AFX2-DIP_0
designator USB?, comment USB3_0_SMDx1
USB,TYPE-A,2PORT,R/A,W/SHIELD; VSTNO: H00025; Altium-Right: 90; Altium-Bottom: 100
pins: 1 VBUS, 2 D-, 3 D+, 4 GND1, 5 SSRX-, 6 SSRX+, 7 GND2, 8 SSTX-, 9 SSTX+, 10 SHIELD1, 11 SHIELD2

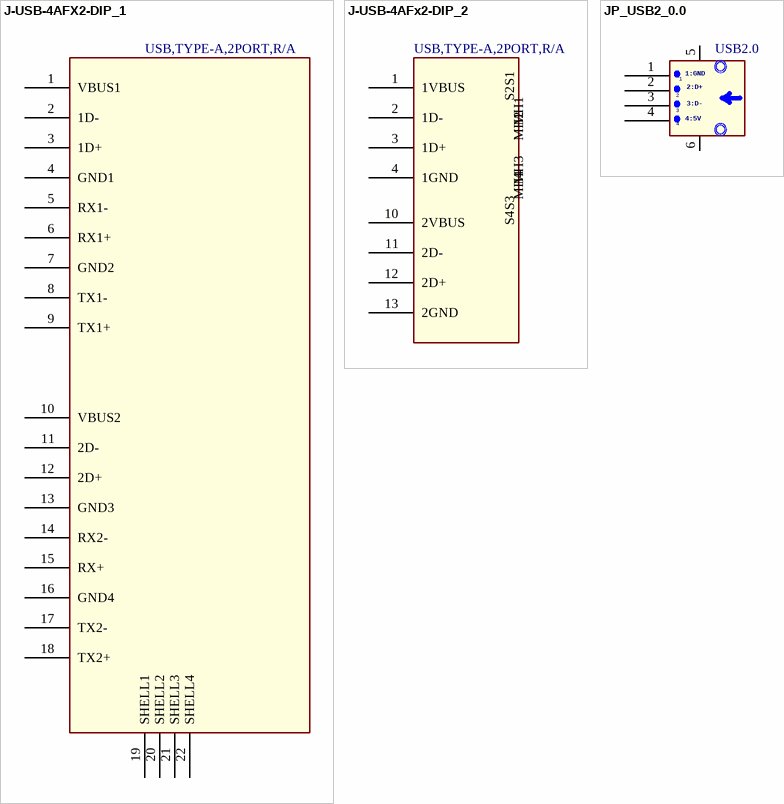
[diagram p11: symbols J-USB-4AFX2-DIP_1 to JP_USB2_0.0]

## J-USB-4AFX2-DIP_1
designator USB?, comment USB,TYPE-A,2PORT,R/A
USB,TYPE-A,2PORT,R/A,W/SHIELD; VSTNO: H00025; Altium-Right: 160; Altium-Bottom: 450
pins: 1 VBUS1, 2 1D-, 3 1D+, 4 GND1, 5 RX1-, 6 RX1+, 7 GND2, 8 TX1-, 9 TX1+, 10 VBUS2, 11 2D-, 12 2D+, 13 GND3, 14 RX2-, 15 RX+, 16 GND4, 17 TX2-, 18 TX2+, 19 SHELL1, 20 SHELL2, 21 SHELL3, 22 SHELL4

## J-USB-4AFx2-DIP_2
designator USB?, comment USB,TYPE-A,2PORT,R/A
USB,TYPE-A,2PORT,R/A,W/SHIELD; VSTNO: H00025; Altium-Right: 70; Altium-Bottom: 190
pins: 1 1VBUS, 2 1D-, 3 1D+, 4 1GND, 10 2VBUS, 11 2D-, 12 2D+, 13 2GND, S1 MH1, S2 MH2, S3 MH3, S4 MH4

## JP_USB2_0.0
designator USB?, comment USB2.0
PCB Footprint: USB20; Altium-Right: 50
footprint USB20
pins: 1, 2, 3, 4, 5, 6

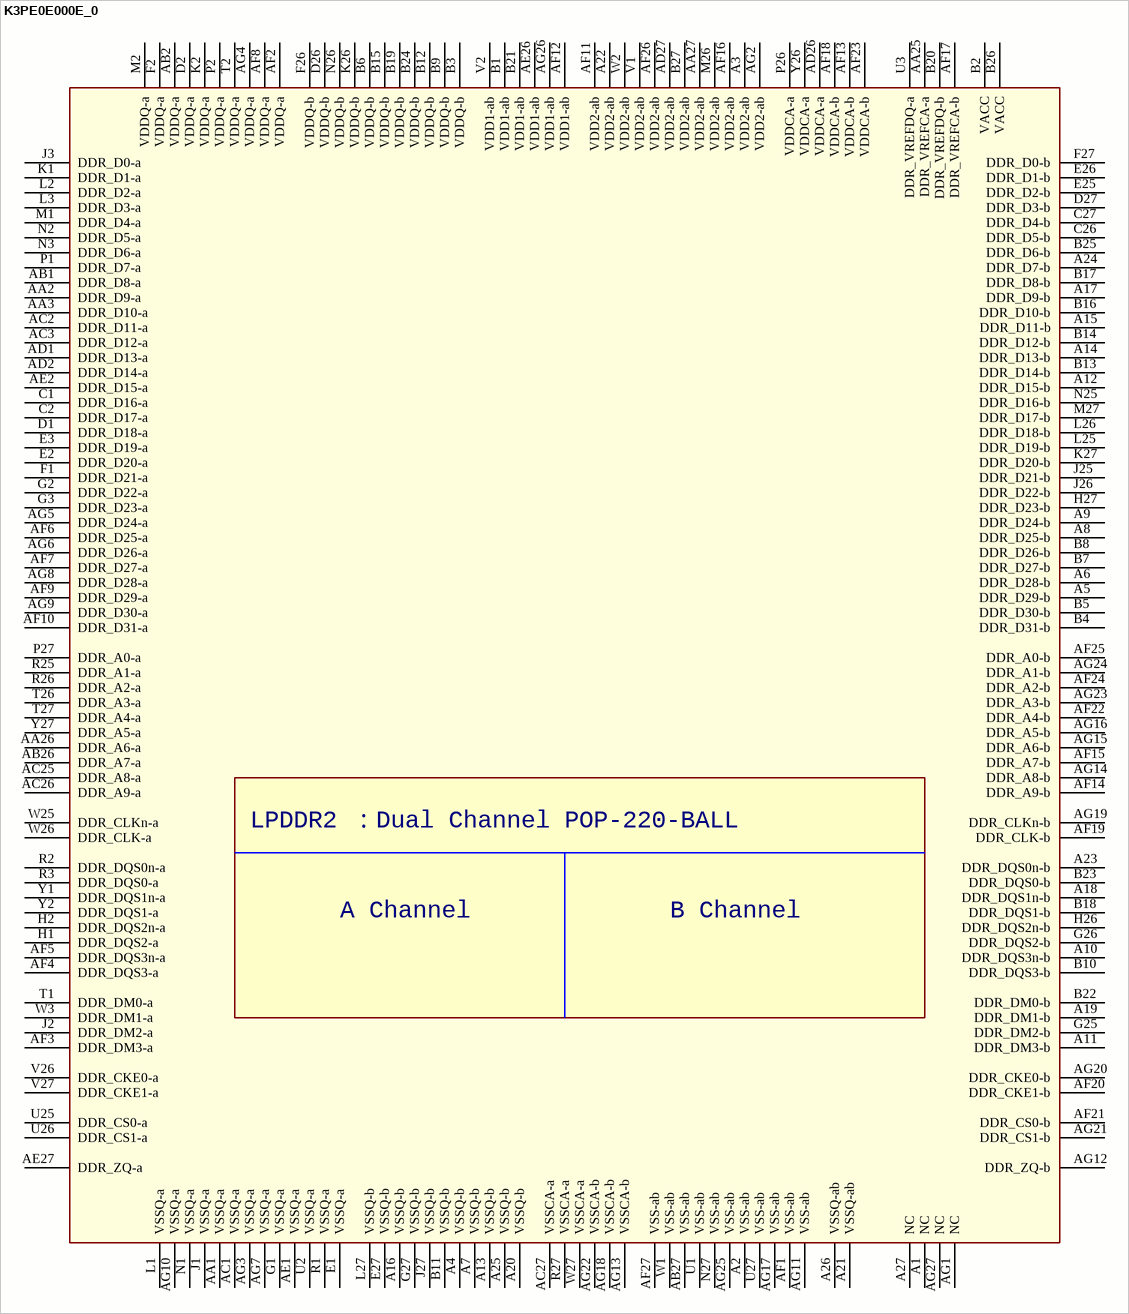
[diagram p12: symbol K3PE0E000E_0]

## K3PE0E000E_0
designator U?
Altium-Right: 660; Altium-Bottom: 770
footprint FBGA220-14X14
pins: A1 NC, A2 VSS-ab, A3 VDD2-ab, A4 VSSQ-b, A5 DDR_D29-b, A6 DDR_D28-b, A7 VSSQ-b, A8 DDR_D25-b, A9 DDR_D24-b, A10 DDR_DQS3n-b, A11 DDR_DM3-b, A12 DDR_D15-b, A13 VSSQ-b, A14 DDR_D13-b, A15 DDR_D11-b, A16 VSSQ-b, A17 DDR_D9-b, A18 DDR_DQS1n-b, A19 DDR_DM1-b, A20 VSSQ-b, A21 VSSQ-ab, A22 VDD2-ab, A23 DDR_DQS0n-b, A24 DDR_D7-b, A25 VSSQ-b, A26 VSSQ-ab, A27 NC, AA1 VSSQ-a, AA2 DDR_D9-a, AA3 DDR_D10-a, AA25 DDR_VREFCA-a, AA26 DDR_A6-a, AA27 VDD2-ab, AB1 DDR_D8-a, AB2 VDDQ-a, AB26 DDR_A7-a, AB27 VSS-ab, AC1 VSSQ-a, AC2 DDR_D11-a, AC3 DDR_D12-a, AC25 DDR_A8-a, AC26 DDR_A9-a, AC27 VSSCA-a, AD1 DDR_D13-a, AD2 DDR_D14-a, AD26 VDDCA-a, AD27 VDD2-ab, AE1 VSSQ-a, AE2 DDR_D15-a, AE26 VDD1-ab, AE27 DDR_ZQ-a, AF1 VSS-ab, AF2 VDDQ-a, AF3 DDR_DM3-a, AF4 DDR_DQS3-a, AF5 DDR_DQS3n-a, AF6 DDR_D25-a, AF7 DDR_D27-a, AF8 VDDQ-a, AF9 DDR_D29-a, AF10 DDR_D31-a, AF11 VDD2-ab, AF12 VDD1-ab, AF13 VDDCA-b, AF14 DDR_A9-b, AF15 DDR_A7-b, AF16 VDD2-ab, AF17 DDR_VREFCA-b, AF18 VDDCA-b, AF19 DDR_CLK-b, AF20 DDR_CKE1-b, AF21 DDR_CS0-b, AF22 DDR_A4-b, AF23 VDDCA-b, AF24 DDR_A2-b, AF25 DDR_A0-b, AF26 VDD2-ab, AF27 VSS-ab, AG1 NC, AG2 VDD2-ab, AG3 VSSQ-a, AG4 VDDQ-a, AG5 DDR_D24-a, AG6 DDR_D26-a, AG7 VSSQ-a, AG8 DDR_D28-a, AG9 DDR_D30-a, AG10 VSSQ-a, AG11 VSS-ab, AG12 DDR_ZQ-b, AG13 VSSCA-b, AG14 DDR_A8-b, AG15 DDR_A6-b, AG16 DDR_A5-b, AG17 VSS-ab, AG18 VSSCA-b, AG19 DDR_CLKn-b, AG20 DDR_CKE0-b, AG21 DDR_CS1-b, AG22 VSSCA-b, AG23 DDR_A3-b, AG24 DDR_A1-b, AG25 VSS-ab, AG26 VDD1-ab, AG27 NC, B1 VDD1-ab, B2 VACC, B3 VDDQ-b, B4 DDR_D31-b, B5 DDR_D30-b, B6 VDDQ-b, B7 DDR_D27-b, B8 DDR_D26-b, B9 VDDQ-b, B10 DDR_DQS3-b, B11 VSSQ-b, B12 VDDQ-b, B13 DDR_D14-b, B14 DDR_D12-b, B15 VDDQ-b, B16 DDR_D10-b, B17 DDR_D8-b, B18 DDR_DQS1-b, B19 VDDQ-b, B20 DDR_VREFDQ-b, B21 VDD1-ab, B22 DDR_DM0-b, B23 DDR_DQS0-b, B24 VDDQ-b, B25 DDR_D6-b, B26 VACC, B27 VDD2-ab, C1 DDR_D16-a, C2 DDR_D17-a, C26 DDR_D5-b, C27 DDR_D4-b, D1 DDR_D18-a, D2 VDDQ-a, D26 VDDQ-b, D27 DDR_D3-b, E1 VSSQ-a, E2 DDR_D20-a, E3 DDR_D19-a, E25 DDR_D2-b, E26 DDR_D1-b, E27 VSSQ-b, F1 DDR_D21-a, F2 VDDQ-a, F26 VDDQ-b, F27 DDR_D0-b, G1 VSSQ-a, G2 DDR_D22-a, G3 DDR_D23-a, G25 DDR_DM2-b, G26 DDR_DQS2-b, G27 VSSQ-b, H1 DDR_DQS2-a, H2 DDR_DQS2n-a, H26 DDR_DQS2n-b, H27 DDR_D23-b, J1 VSSQ-a, J2 DDR_DM2-a, J3 DDR_D0-a, J25 DDR_D21-b, J26 DDR_D22-b, J27 VSSQ-b, K1 DDR_D1-a, K2 VDDQ-a, K26 VDDQ-b, K27 DDR_D20-b, L1 VSSQ-a, L2 DDR_D2-a, L3 DDR_D3-a, L25 DDR_D19-b, L26 DDR_D18-b, L27 VSSQ-b, M1 DDR_D4-a, M2 VDDQ-a, M26 VDD2-ab, M27 DDR_D17-b, N1 VSSQ-a, N2 DDR_D5-a, N3 DDR_D6-a, N25 DDR_D16-b, N26 VDDQ-b, N27 VSS-ab, P1 DDR_D7-a, P2 VDDQ-a, P26 VDDCA-a, P27 DDR_A0-a, R1 VSSQ-a, R2 DDR_DQS0n-a, R3 DDR_DQS0-a, R25 DDR_A1-a, R26 DDR_A2-a, R27 VSSCA-a, T1 DDR_DM0-a, T2 VDDQ-a, T26 DDR_A3-a, T27 DDR_A4-a, U1 VSS-ab, U2 VSSQ-a, U3 DDR_VREFDQ-a, U25 DDR_CS0-a, U26 DDR_CS1-a, U27 VSS-ab, V1 VDD2-ab, V2 VDD1-ab, V26 DDR_CKE0-a, V27 DDR_CKE1-a, W1 VSS-ab, W2 VDD2-ab, W3 DDR_DM1-a, W25 DDR_CLKn-a, W26 DDR_CLK-a, W27 VSSCA-a, Y1 DDR_DQS1n-a, Y2 DDR_DQS1-a, Y26 VDDCA-a, Y27 DDR_A5-a

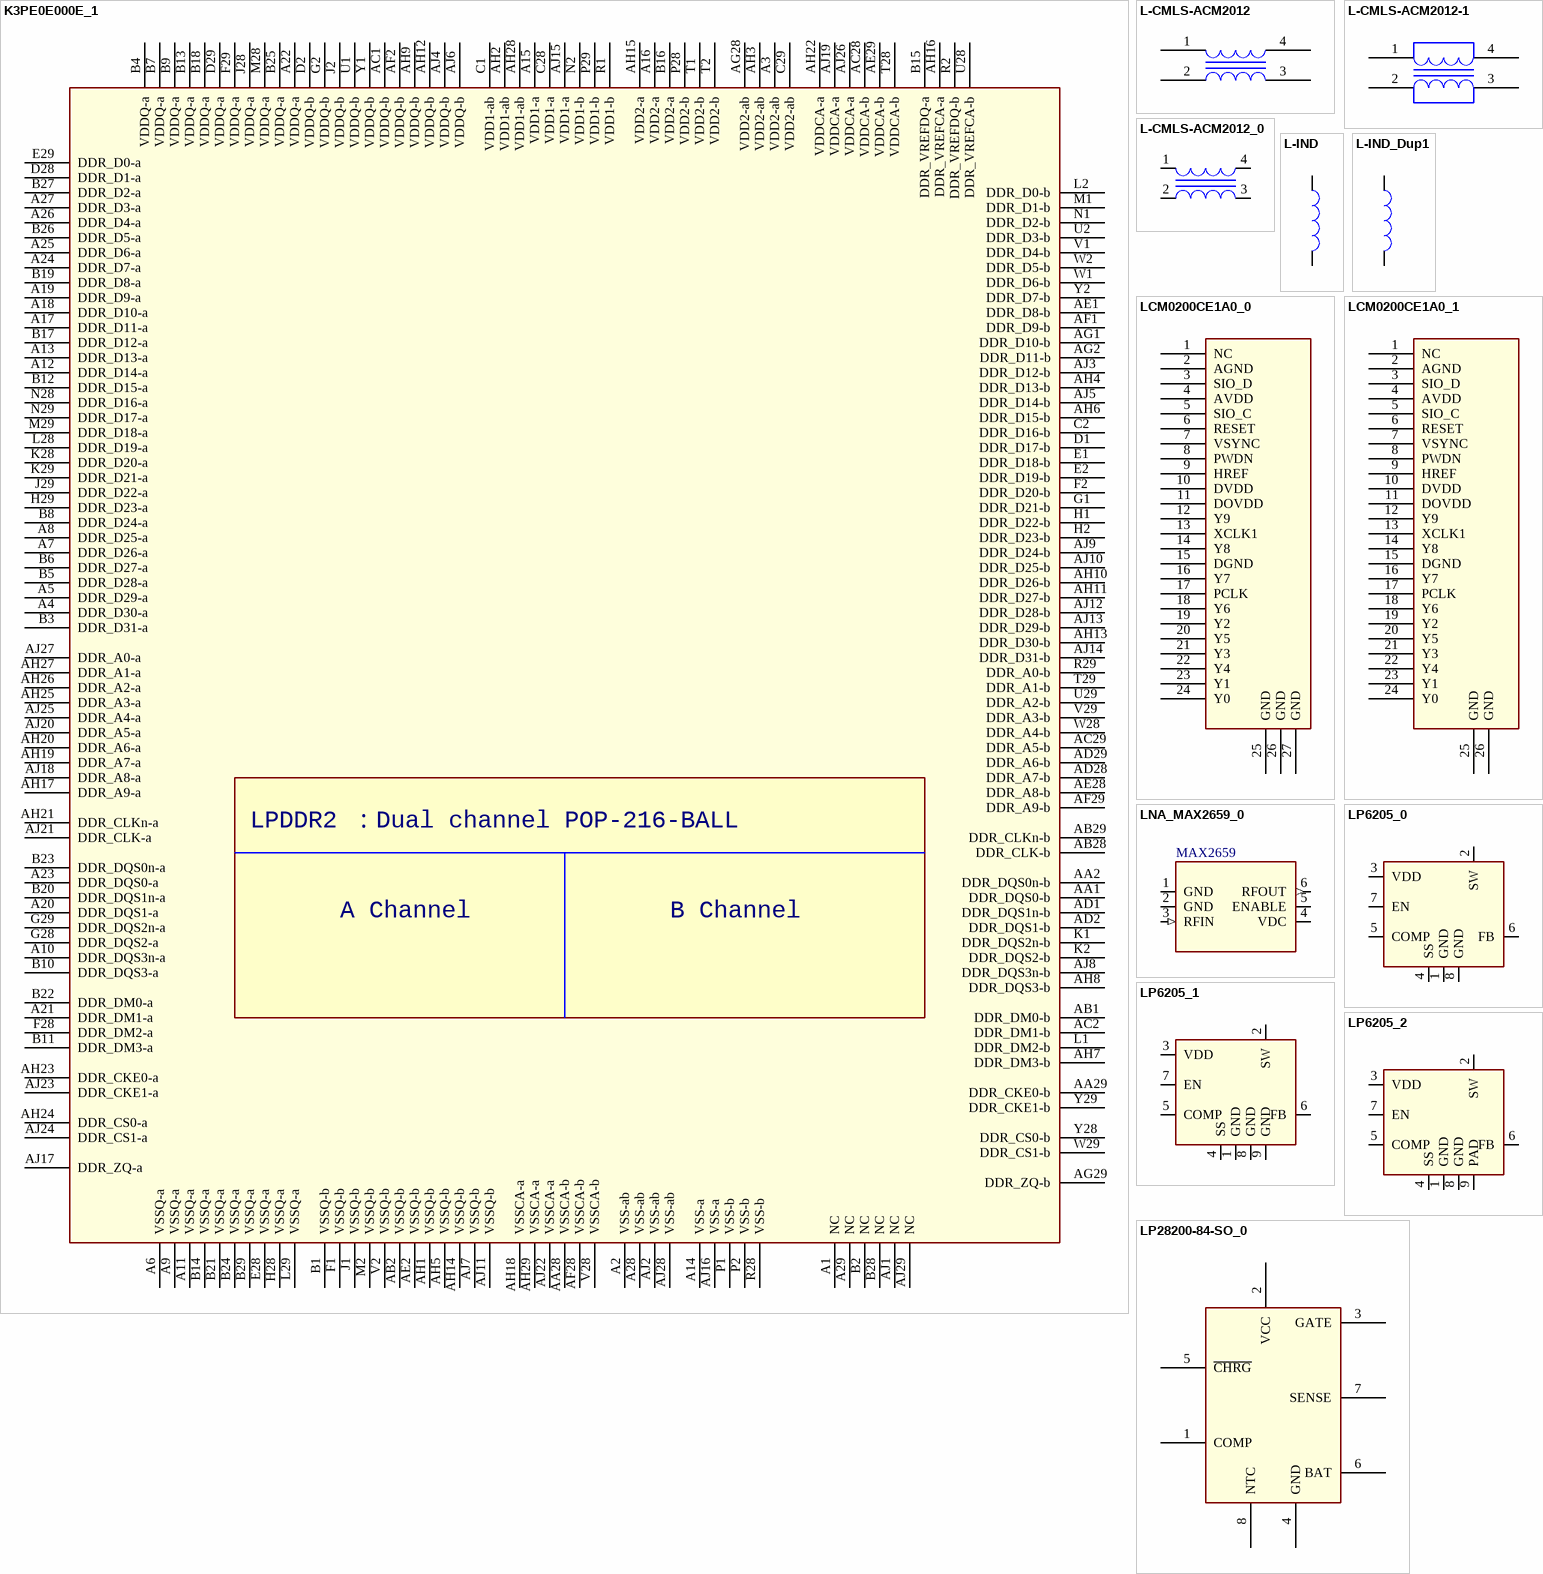
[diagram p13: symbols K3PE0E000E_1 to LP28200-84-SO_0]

## K3PE0E000E_1
designator U?
Altium-Right: 660; Altium-Bottom: 770
footprint FBGA220-14X14
pins: A1 NC, A2 VSS-ab, A3 VDD2-ab, A4 DDR_D30-a, A5 DDR_D29-a, A6 VSSQ-a, A7 DDR_D26-a, A8 DDR_D25-a, A9 VSSQ-a, A10 DDR_DQS3n-a, A11 VSSQ-a, A12 DDR_D14-a, A13 DDR_D13-a, A14 VSS-a, A15 VDD1-a, A16 VDD2-a, A17 DDR_D11-a, A18 DDR_D10-a, A19 DDR_D9-a, A20 DDR_DQS1-a, A21 DDR_DM1-a, A22 VDDQ-a, A23 DDR_DQS0-a, A24 DDR_D7-a, A25 DDR_D6-a, A26 DDR_D4-a, A27 DDR_D3-a, A28 VSS-ab, A29 NC, AA1 DDR_DQS0-b, AA2 DDR_DQS0n-b, AA28 VSSCA-b, AA29 DDR_CKE0-b, AB1 DDR_DM0-b, AB2 VSSQ-b, AB28 DDR_CLK-b, AB29 DDR_CLKn-b, AC1 VDDQ-b, AC2 DDR_DM1-b, AC28 VDDCA-b, AC29 DDR_A5-b, AD1 DDR_DQS1n-b, AD2 DDR_DQS1-b, AD28 DDR_A7-b, AD29 DDR_A6-b, AE1 DDR_D8-b, AE2 VSSQ-b, AE28 DDR_A8-b, AE29 VDDCA-b, AF1 DDR_D9-b, AF2 VDDQ-b, AF28 VSSCA-b, AF29 DDR_A9-b, AG1 DDR_D10-b, AG2 DDR_D11-b, AG28 VDD2-ab, AG29 DDR_ZQ-b, AH1 VSSQ-b, AH2 VDD1-ab, AH3 VDD2-ab, AH4 DDR_D13-b, AH5 VSSQ-b, AH6 DDR_D15-b, AH7 DDR_DM3-b, AH8 DDR_DQS3-b, AH9 VDDQ-b, AH10 DDR_D26-b, AH11 DDR_D27-b, AH12 VDDQ-b, AH13 DDR_D30-b, AH14 VSSQ-b, AH15 VDD2-a, AH16 DDR_VREFCA-a, AH17 DDR_A9-a, AH18 VSSCA-a, AH19 DDR_A7-a, AH20 DDR_A6-a, AH21 DDR_CLKn-a, AH22 VDDCA-a, AH23 DDR_CKE0-a, AH24 DDR_CS0-a, AH25 DDR_A3-a, AH26 DDR_A2-a, AH27 DDR_A1-a, AH28 VDD1-ab, AH29 VSSCA-a, AJ1 NC, AJ2 VSS-ab, AJ3 DDR_D12-b, AJ4 VDDQ-b, AJ5 DDR_D14-b, AJ6 VDDQ-b, AJ7 VSSQ-b, AJ8 DDR_DQS3n-b, AJ9 DDR_D24-b, AJ10 DDR_D25-b, AJ11 VSSQ-b, AJ12 DDR_D28-b, AJ13 DDR_D29-b, AJ14 DDR_D31-b, AJ15 VDD1-a, AJ16 VSS-a, AJ17 DDR_ZQ-a, AJ18 DDR_A8-a, AJ19 VDDCA-a, AJ20 DDR_A5-a, AJ21 DDR_CLK-a, AJ22 VSSCA-a, AJ23 DDR_CKE1-a, AJ24 DDR_CS1-a, AJ25 DDR_A4-a, AJ26 VDDCA-a, AJ27 DDR_A0-a, AJ28 VSS-ab, AJ29 NC, B1 VSSQ-b, B2 NC, B3 DDR_D31-a, B4 VDDQ-a, B5 DDR_D28-a, B6 DDR_D27-a, B7 VDDQ-a, B8 DDR_D24-a, B9 VDDQ-a, B10 DDR_DQS3-a, B11 DDR_DM3-a, B12 DDR_D15-a, B13 VDDQ-a, B14 VSSQ-a, B15 DDR_VREFDQ-a, B16 VDD2-a, B17 DDR_D12-a, B18 VDDQ-a, B19 DDR_D8-a, B20 DDR_DQS1n-a, B21 VSSQ-a, B22 DDR_DM0-a, B23 DDR_DQS0n-a, B24 VSSQ-a, B25 VDDQ-a, B26 DDR_D5-a, B27 DDR_D2-a, B28 NC, B29 VSSQ-a, C1 VDD1-ab, C2 DDR_D16-b, C28 VDD1-a, C29 VDD2-ab, D1 DDR_D17-b, D2 VDDQ-b, D28 DDR_D1-a, D29 VDDQ-a, E1 DDR_D18-b, E2 DDR_D19-b, E28 VSSQ-a, E29 DDR_D0-a, F1 VSSQ-b, F2 DDR_D20-b, F28 DDR_DM2-a, F29 VDDQ-a, G1 DDR_D21-b, G2 VDDQ-b, G28 DDR_DQS2-a, G29 DDR_DQS2n-a, H1 DDR_D22-b, H2 DDR_D23-b, H28 VSSQ-a, H29 DDR_D23-a, J1 VSSQ-b, J2 VDDQ-b, J28 VDDQ-a, J29 DDR_D22-a, K1 DDR_DQS2n-b, K2 DDR_DQS2-b, K28 DDR_D20-a, K29 DDR_D21-a, L1 DDR_DM2-b, L2 DDR_D0-b, L28 DDR_D19-a, L29 VSSQ-a, M1 DDR_D1-b, M2 VSSQ-b, M28 VDDQ-a, M29 DDR_D18-a, N1 DDR_D2-b, N2 VDD1-b, N28 DDR_D16-a, N29 DDR_D17-a, P1 VSS-b, P2 VSS-b, P28 VDD2-b, P29 VDD1-b, R1 VDD1-b, R2 DDR_VREFDQ-b, R28 VSS-b, R29 DDR_A0-b, T1 VDD2-b, T2 VDD2-b, T28 VDDCA-b, T29 DDR_A1-b, U1 VDDQ-b, U2 DDR_D3-b, U28 DDR_VREFCA-b, U29 DDR_A2-b, V1 DDR_D4-b, V2 VSSQ-b, V28 VSSCA-b, V29 DDR_A3-b, W1 DDR_D6-b, W2 DDR_D5-b, W28 DDR_A4-b, W29 DDR_CS1-b, Y1 VDDQ-b, Y2 DDR_D7-b, Y28 DDR_CS0-b, Y29 DDR_CKE1-b

## L-CMLS-ACM2012
designator CMLP?
Altium-Right: 40; Altium-Bottom: 20
pins: 1, 2, 3, 4

## L-CMLS-ACM2012-1
designator CMLP?
Altium-Right: 40
pins: 1, 2, 3, 4

## L-CMLS-ACM2012_0
designator CMLP?
Altium-Right: 40; Altium-Bottom: 20
pins: 1, 2, 3, 4

## L-IND
designator L?
Altium-Right: 10; Altium-Bottom: 40
pins: 1, 2

## L-IND_Dup1
designator L?
Altium-Right: 10; Altium-Bottom: 40
pins: 1, 2

## LCM0200CE1A0_0
designator U?
Altium-Right: 70; Altium-Bottom: 260
pins: 1 NC, 2 AGND, 3 SIO_D, 4 AVDD, 5 SIO_C, 6 RESET, 7 VSYNC, 8 PWDN, 9 HREF, 10 DVDD, 11 DOVDD, 12 Y9, 13 XCLK1, 14 Y8, 15 DGND, 16 Y7, 17 PCLK, 18 Y6, 19 Y2, 20 Y5, 21 Y3, 22 Y4, 23 Y1, 24 Y0, 25 GND, 26 GND, 27 GND

## LCM0200CE1A0_1
designator U?
Altium-Right: 70; Altium-Bottom: 260
pins: 1 NC, 2 AGND, 3 SIO_D, 4 AVDD, 5 SIO_C, 6 RESET, 7 VSYNC, 8 PWDN, 9 HREF, 10 DVDD, 11 DOVDD, 12 Y9, 13 XCLK1, 14 Y8, 15 DGND, 16 Y7, 17 PCLK, 18 Y6, 19 Y2, 20 Y5, 21 Y3, 22 Y4, 23 Y1, 24 Y0, 25 GND, 26 GND

## LNA_MAX2659_0
designator U?, comment MAX2659
Altium-Right: 80; Altium-Bottom: 60
footprint P-TSLP-7-1
pins: 1 GND (power), 2 GND, 3 RFIN (in), 4 VDC (power), 5 ENABLE, 6 RFOUT (out)

## LP6205_0
designator U?
Altium-Right: 80; Altium-Bottom: 70
pins: 1 GND, 2 SW, 3 VDD, 4 SS, 5 COMP, 6 FB, 7 EN, 8 GND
